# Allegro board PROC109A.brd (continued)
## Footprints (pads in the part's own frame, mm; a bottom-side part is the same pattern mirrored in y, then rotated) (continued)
HDR_2X5_61301021121_S_T_8-6
  rect 1.803x1.803 hole 1.118: 1(0,0)
  round 1.803 hole 1.118: 2(0,2.54) 3(2.54,0) 4(2.54,2.54) 5(5.08,0) 6(5.08,2.54) 7(7.62,0) 8(7.62,2.54) 9(10.16,0) 10(10.16,2.54)
IND4_DLW21H_90X60_SMD_1-4
  rect 0.889x0.356 smd: 1(-0.85,-0.425) 2(0.85,-0.425) 3(0.85,0.425) 4(-0.85,0.425)
IND0603_1
  rect 0.914x1.016 smd: 1(-0.8,0) 2(0.8,0)
IND0603_1#2
  rect 1.245x1.092 smd: 1(-0.85,0) 2(0.85,0)
IND0806_1-2
  rect 1.219x1.803 smd: 1(-0.85,0) 2(0.85,0)
LED4_150066RV54050_70X60_SMD_0-7
  rect 0.787x0.508 smd: 1(-0.8,-0.45) 2(0.8,-0.45) 3(0.8,0.45) 4(-0.8,0.45)
LED_0603
  rect 0.787x0.787 smd: 1(-0.749,0) 2(0.749,0)
LED_150040GS73220_40X20_SMD_0-4
  rect 0.406x0.457 smd: 1(-0.5,0) 2(0.5,0)
LED_150060SS75000_70X40_SMD_0-8
  rect 0.787x0.787 smd: 1(-0.8,0) 2(0.8,0)
MSOP10_19-68_120X120_1-1
  rect 1.448x0.305 smd: 1(-2.2,1) 2(-2.2,0.5) 3(-2.2,0) 4(-2.2,-0.5) 5(-2.2,-1) 6(2.2,-1) 7(2.2,-0.5) 8(2.2,0) 9(2.2,0.5) 10(2.2,1)
OSC4_ASEK_130X100_SMD_1-2
  rect 1.397x0.991 smd: 1(-1.1,-0.8) 2(1.1,-0.8) 3(1.1,0.8) 4(-1.1,0.8)
QFN16_19-68_120X120_1_EP1-6
  rect 0.838x0.254 smd: 1(-1.45,0.75) 2(-1.45,0.25) 3(-1.45,-0.25) 4(-1.45,-0.75) 9(1.45,-0.75) 10(1.45,-0.25) 11(1.45,0.25) 12(1.45,0.75)
  rect 0.254x0.838 smd: 5(-0.75,-1.45) 6(-0.25,-1.45) 7(0.25,-1.45) 8(0.75,-1.45) 13(0.75,1.45) 14(0.25,1.45) 15(-0.25,1.45) 16(-0.75,1.45)
  rect 1.6x1.6 smd: 17(0,0)
QFN16_19-68_160X140_1
  rect 0.864x0.279 smd: 1(-1.975,-0.75) 8(1.975,-0.75) 9(1.975,0.75) 16(-1.975,0.75)
  rect 0.279x0.864 smd: 2(-1.25,-1.725) 3(-0.75,-1.725) 4(-0.25,-1.725) 5(0.25,-1.725) 6(0.75,-1.725) 7(1.25,-1.725) 10(1.25,1.725) 11(0.75,1.725) 12(0.25,1.725) 13(-0.25,1.725) 14(-0.75,1.725) 15(-1.25,1.725)
  rect 2.54x2.057 smd: 17(0,0)
QFN20_19-68_160X160_1
  rect 0.889x0.305 smd: 1(-2.05,1) 2(-2.05,0.5) 3(-2.05,0) 4(-2.05,-0.5) 5(-2.05,-1) 11(2.05,-1) 12(2.05,-0.5) 13(2.05,0) 14(2.05,0.5) 15(2.05,1)
  rect 0.305x0.889 smd: 6(-1,-2.05) 7(-0.5,-2.05) 8(0,-2.05) 9(0.5,-2.05) 10(1,-2.05) 16(1,2.05) 17(0.5,2.05) 18(0,2.05) 19(-0.5,2.05) 20(-1,2.05)
  rect 2.794x2.794 smd: 21(0,0)
QFN24_19-68_220X140_1
  rect 0.838x0.279 smd: 1(-2.725,-0.75) 12(2.725,-0.75) 13(2.725,0.75) 24(-2.725,0.75)
  rect 0.279x0.838 smd: 2(-2.25,-1.725) 3(-1.75,-1.725) 4(-1.25,-1.725) 5(-0.75,-1.725) 6(-0.25,-1.725) 7(0.25,-1.725) 8(0.75,-1.725) 9(1.25,-1.725) 10(1.75,-1.725) 11(2.25,-1.725) 14(2.25,1.725) 15(1.75,1.725) 16(1.25,1.725) 17(0.75,1.725) 18(0.25,1.725) 19(-0.25,1.725) 20(-0.75,1.725) 21(-1.25,1.725) 22(-1.75,1.725) 23(-2.25,1.725)
  custom 0.508x0.508 smd: 25(0,0)
QFN48_19-68_280X280_1_EP4-2
  rect 0.838x0.305 smd: 1(-3.5,2.75) 2(-3.5,2.25) 3(-3.5,1.75) 4(-3.5,1.25) 5(-3.5,0.75) 6(-3.5,0.25) 7(-3.5,-0.25) 8(-3.5,-0.75) 9(-3.5,-1.25) 10(-3.5,-1.75) 11(-3.5,-2.25) 12(-3.5,-2.75) 25(3.5,-2.75) 26(3.5,-2.25) 27(3.5,-1.75) 28(3.5,-1.25) 29(3.5,-0.75) 30(3.5,-0.25) 31(3.5,0.25) 32(3.5,0.75) 33(3.5,1.25) 34(3.5,1.75) 35(3.5,2.25) 36(3.5,2.75)
  rect 0.305x0.838 smd: 13(-2.75,-3.5) 14(-2.25,-3.5) 15(-1.75,-3.5) 16(-1.25,-3.5) 17(-0.75,-3.5) 18(-0.25,-3.5) 19(0.25,-3.5) 20(0.75,-3.5) 21(1.25,-3.5) 22(1.75,-3.5) 23(2.25,-3.5) 24(2.75,-3.5) 37(2.75,3.5) 38(2.25,3.5) 39(1.75,3.5) 40(1.25,3.5) 41(0.75,3.5) 42(0.25,3.5) 43(-0.25,3.5) 44(-0.75,3.5) 45(-1.25,3.5) 46(-1.75,3.5) 47(-2.25,3.5) 48(-2.75,3.5)
  rect 4.191x4.191 smd: 49(0,0)
RECPT_2X10_CRD-081413-A_S_T_8-6
  rect 1.88x1.88 hole 1.168: 1(0,0)
  round 1.88 hole 1.168: 2(0,-2.54) 3(2.54,0) 4(2.54,-2.54) 5(5.08,0) 6(5.08,-2.54) 7(7.62,0) 8(7.62,-2.54) 9(10.16,0) 10(10.16,-2.54) 11(12.7,0) 12(12.7,-2.54) 13(15.24,0) 14(15.24,-2.54) 15(17.78,0) 16(17.78,-2.54) 17(20.32,0) 18(20.32,-2.54) 19(22.86,0) 20(22.86,-2.54)
RES0201_0-5
  rect 0.457x0.432 smd: 1(-0.33,0) 2(0.33,0)
RES0402_0-5
  rect 0.559x0.635 smd: 1(-0.49,0) 2(0.49,0)
RES0406_0-5
  rect 0.559x1.753 smd: 1(-0.49,0) 2(0.49,0)
RES0603_0-75
  rect 0.635x0.991 smd: 1(-0.74,0) 2(0.74,0)
SC70-5_1-1
  rect 0.94x0.406 smd: 1(-1.1,0.65) 2(-1.1,0) 3(-1.1,-0.65) 4(1.1,-0.65) 5(1.1,0.65)
SC70-6
  rect 0.94x0.406 smd: 1(-1.1,0.65) 2(-1.1,0) 3(-1.1,-0.65) 4(1.1,-0.65) 5(1.1,0) 6(1.1,0.65)
SOIC16_1-8
  rect 1.549x0.61 smd: 1(-2.7,4.445) 2(-2.7,3.175) 3(-2.7,1.905) 4(-2.7,0.635) 5(-2.7,-0.635) 6(-2.7,-1.905) 7(-2.7,-3.175) 8(-2.7,-4.445) 9(2.7,-4.445) 10(2.7,-3.175) 11(2.7,-1.905) 12(2.7,-0.635) 13(2.7,0.635) 14(2.7,1.905) 15(2.7,3.175) 16(2.7,4.445)
SOIC16_W_2-7
  rect 2.007x0.61 smd: 1(-4.65,4.445) 2(-4.65,3.175) 3(-4.65,1.905) 4(-4.65,0.635) 5(-4.65,-0.635) 6(-4.65,-1.905) 7(-4.65,-3.175) 8(-4.65,-4.445) 9(4.65,-4.445) 10(4.65,-3.175) 11(4.65,-1.905) 12(4.65,-0.635) 13(4.65,0.635) 14(4.65,1.905) 15(4.65,3.175) 16(4.65,4.445)
SON6_25-59_85X85_0-8
  rect 0.61x0.356 smd: 1(-1.05,0.65) 2(-1.05,0) 3(-1.05,-0.65) 4(1.05,-0.65) 5(1.05,0) 6(1.05,0.65)
  rect 1.092x1.702 smd: 7(0,0)
SON6_CSD17313Q2_80X80
  rect 0.406x0.457 smd: 1(-0.65,-0.922) 2(0,-0.922) 3(0.65,-0.922) 4(0.65,0.922) 5(0,0.922) 6(-0.65,0.922)
  rect 0.406x0.864 smd: 7(0.65,0.096)
  rect 1.041x1.092 smd: 8(-0.325,0)
SON8_25-59_130X130_1
  rect 0.762x0.356 smd: 1(-1.45,0.975) 2(-1.45,0.325) 3(-1.45,-0.325) 4(-1.45,-0.975) 5(1.45,-0.975) 6(1.45,-0.325) 7(1.45,0.325) 8(1.45,0.975)
  rect 1.753x2.515 smd: 9(0,0)
SOT23-5
  rect 1.092x0.61 smd: 1(-1.3,0.95) 2(-1.3,0) 3(-1.3,-0.95) 4(1.3,-0.95) 5(1.3,0.95)
SOT23-5_1-5
  rect 1.295x0.66 smd: 1(-1.4,0.95) 2(-1.4,0) 3(-1.4,-0.95) 4(1.4,-0.95) 5(1.4,0.95)
SOT23-5_1-5#2
  rect 1.092x0.61 smd: 1(-1.3,0.95) 2(-1.3,0) 3(-1.3,-0.95) 4(1.3,-0.95) 5(1.3,0.95)
SOT23-123_1-2
  rect 1.016x0.61 smd: 1(-1.15,0.95) 2(-1.15,-0.95) 3(1.15,0)
SOT553-5_0-6
  rect 0.762x0.305 smd: 1(-0.79,0.5) 2(-0.79,0) 3(-0.79,-0.5) 4(0.79,-0.5) 5(0.79,0.5)
SW4_436331045822_190X190_SMD_1-7
  round 0.686 hole 0.813 unplated: (0,1.375) (0,-1.375)
  rect 1.194x0.991 smd: 1(2.8,0.85) 2(2.8,-0.85) 3(-2.8,0.85) 4(-2.8,-0.85)
SW16_416131160808_460X230_SMD_2-7
  rect 0.762x1.27 smd: 1(-4.445,-3.81) 2(-3.175,-3.81) 3(-1.905,-3.81) 4(-0.635,-3.81) 5(0.635,-3.81) 6(1.905,-3.81) 7(3.175,-3.81) 8(4.445,-3.81) 9(4.445,3.81) 10(3.175,3.81) 11(1.905,3.81) 12(0.635,3.81) 13(-0.635,3.81) 14(-1.905,3.81) 15(-3.175,3.81) 16(-4.445,3.81)
SW_TDA01H0S_240X90_SMD_2-3
  rect 1.27x0.762 smd: 1(-3.81,0) 2(3.81,0)
TP20_SMD
  round 0.508 smd: 1(0,0)
TP40_SMD
  round 1.016 smd: 1(0,0)
TP_40X65
  round 1.651 hole 1.016: 1(0,0)
TQFN42_19-68_140X360_0-8
  rect 0.838x0.305 smd: 1(-1.7,4) 2(-1.7,3.5) 3(-1.7,3) 4(-1.7,2.5) 5(-1.7,2) 6(-1.7,1.5) 7(-1.7,1) 8(-1.7,0.5) 9(-1.7,0) 10(-1.7,-0.5) 11(-1.7,-1) 12(-1.7,-1.5) 13(-1.7,-2) 14(-1.7,-2.5) 15(-1.7,-3) 16(-1.7,-3.5) 17(-1.7,-4) 22(1.7,-4) 23(1.7,-3.5) 24(1.7,-3) 25(1.7,-2.5) 26(1.7,-2) 27(1.7,-1.5) 28(1.7,-1) 29(1.7,-0.5) 30(1.7,0) 31(1.7,0.5) 32(1.7,1) 33(1.7,1.5) 34(1.7,2) 35(1.7,2.5) 36(1.7,3) 37(1.7,3.5) 38(1.7,4)
  rect 0.305x0.838 smd: 18(-0.75,-4.45) 19(-0.25,-4.45) 20(0.25,-4.45) 21(0.75,-4.45) 39(0.75,4.45) 40(0.25,4.45) 41(-0.25,4.45) 42(-0.75,4.45)
  rect 2.159x7.645 smd: 43(0,0)
TQFP128_15-74_550X550_1-2
  rect 1.499x0.203 smd: 1(-7.7,6.2) 2(-7.7,5.8) 3(-7.7,5.4) 4(-7.7,5) 5(-7.7,4.6) 6(-7.7,4.2) 7(-7.7,3.8) 8(-7.7,3.4) 9(-7.7,3) 10(-7.7,2.6) 11(-7.7,2.2) 12(-7.7,1.8) 13(-7.7,1.4) 14(-7.7,1) 15(-7.7,0.6) 16(-7.7,0.2) 17(-7.7,-0.2) 18(-7.7,-0.6) 19(-7.7,-1) 20(-7.7,-1.4) 21(-7.7,-1.8) 22(-7.7,-2.2) 23(-7.7,-2.6) 24(-7.7,-3) 25(-7.7,-3.4) 26(-7.7,-3.8) 27(-7.7,-4.2) 28(-7.7,-4.6) 29(-7.7,-5) 30(-7.7,-5.4) 31(-7.7,-5.8) 32(-7.7,-6.2) 65(7.7,-6.2) 66(7.7,-5.8) 67(7.7,-5.4) 68(7.7,-5) 69(7.7,-4.6) 70(7.7,-4.2) 71(7.7,-3.8) 72(7.7,-3.4) 73(7.7,-3) 74(7.7,-2.6) 75(7.7,-2.2) 76(7.7,-1.8) 77(7.7,-1.4) 78(7.7,-1) 79(7.7,-0.6) 80(7.7,-0.2) 81(7.7,0.2) 82(7.7,0.6) 83(7.7,1) 84(7.7,1.4) 85(7.7,1.8) 86(7.7,2.2) 87(7.7,2.6) 88(7.7,3) 89(7.7,3.4) 90(7.7,3.8) 91(7.7,4.2) 92(7.7,4.6) 93(7.7,5) 94(7.7,5.4) 95(7.7,5.8) 96(7.7,6.2)
  rect 0.203x1.499 smd: 33(-6.2,-7.7) 34(-5.8,-7.7) 35(-5.4,-7.7) 36(-5,-7.7) 37(-4.6,-7.7) 38(-4.2,-7.7) 39(-3.8,-7.7) 40(-3.4,-7.7) 41(-3,-7.7) 42(-2.6,-7.7) 43(-2.2,-7.7) 44(-1.8,-7.7) 45(-1.4,-7.7) 46(-1,-7.7) 47(-0.6,-7.7) 48(-0.2,-7.7) 49(0.2,-7.7) 50(0.6,-7.7) 51(1,-7.7) 52(1.4,-7.7) 53(1.8,-7.7) 54(2.2,-7.7) 55(2.6,-7.7) 56(3,-7.7) 57(3.4,-7.7) 58(3.8,-7.7) 59(4.2,-7.7) 60(4.6,-7.7) 61(5,-7.7) 62(5.4,-7.7) 63(5.8,-7.7) 64(6.2,-7.7) 97(6.2,7.7) 98(5.8,7.7) 99(5.4,7.7) 100(5,7.7) 101(4.6,7.7) 102(4.2,7.7) 103(3.8,7.7) 104(3.4,7.7) 105(3,7.7) 106(2.6,7.7) 107(2.2,7.7) 108(1.8,7.7) 109(1.4,7.7) 110(1,7.7) 111(0.6,7.7) 112(0.2,7.7) 113(-0.2,7.7) 114(-0.6,7.7) 115(-1,7.7) 116(-1.4,7.7) 117(-1.8,7.7) 118(-2.2,7.7) 119(-2.6,7.7) 120(-3,7.7) 121(-3.4,7.7) 122(-3.8,7.7) 123(-4.2,7.7) 124(-4.6,7.7) 125(-5,7.7) 126(-5.4,7.7) 127(-5.8,7.7) 128(-6.2,7.7)
TSSOP8_25-59_125X180_1-2
  rect 1.499x0.457 smd: 1(-2.9,0.975) 2(-2.9,0.325) 3(-2.9,-0.325) 4(-2.9,-0.975) 5(2.9,-0.975) 6(2.9,-0.325) 7(2.9,0.325) 8(2.9,0.975)
TSSOP14_25-59_205X180_1-2
  rect 1.499x0.457 smd: 1(-2.9,1.95) 2(-2.9,1.3) 3(-2.9,0.65) 4(-2.9,0) 5(-2.9,-0.65) 6(-2.9,-1.3) 7(-2.9,-1.95) 8(2.9,-1.95) 9(2.9,-1.3) 10(2.9,-0.65) 11(2.9,0) 12(2.9,0.65) 13(2.9,1.3) 14(2.9,1.95)
TSSOP16_25-59_205X180
  rect 1.6x0.356 smd: 1(-2.8,2.275) 2(-2.8,1.625) 3(-2.8,0.975) 4(-2.8,0.325) 5(-2.8,-0.325) 6(-2.8,-0.975) 7(-2.8,-1.625) 8(-2.8,-2.275) 9(2.8,-2.275) 10(2.8,-1.625) 11(2.8,-0.975) 12(2.8,-0.325) 13(2.8,0.325) 14(2.8,0.975) 15(2.8,1.625) 16(2.8,2.275)
unnamed
  round 0.686 hole 0.813 unplated: (-1.27,1.254) (0,1.254) (1.27,1.254)
unnamed#2
  round 3.073 hole 3.2 unplated: (0,0)
unnamed#4
  round 0.686 hole 0.813 unplated: (-1.27,1.254) (-1.27,-1.254) (0,1.254) (0,-1.254) (1.27,1.254) (1.27,-1.254)
UQFN16_TMUX1574_70X100_0-6
  rect 0.711x0.203 smd: 1(-0.75,0.6)
  rect 0.61x0.203 smd: 2(-0.8,0.2) 3(-0.8,-0.2) 4(-0.8,-0.6) 9(0.8,-0.6) 10(0.8,-0.2) 11(0.8,0.2) 12(0.8,0.6)
  rect 0.203x0.61 smd: 5(-0.6,-1.2) 6(-0.2,-1.2) 7(0.2,-1.2) 8(0.6,-1.2) 13(0.6,1.2) 14(0.2,1.2) 15(-0.2,1.2) 16(-0.6,1.2)
USON10_TPD4E05U_40X100_0-6
  rect 0.559x0.305 smd: 1(-0.385,1) 2(-0.385,0.5) 4(-0.385,-0.5) 5(-0.385,-1) 6(0.385,-1) 7(0.385,-0.5) 9(0.385,0.5) 10(0.385,1)
  rect 0.559x0.406 smd: 3(-0.385,0) 8(0.385,0)
VSON10_TPS74801-Q1_120X120_1
  rect 0.61x0.229 smd: 1(-1.4,1) 2(-1.4,0.5) 3(-1.4,0) 4(-1.4,-0.5) 5(-1.4,-1) 6(1.4,-1) 7(1.4,-0.5) 8(1.4,0) 9(1.4,0.5) 10(1.4,1)
  custom 0.412x0.412 smd: 11(0,0)
VSONHR8_TPS62823_60X80_1
  rect 0.559x0.254 smd: 1(-0.675,0.75) 2(-0.675,0.25) 3(-0.675,-0.25) 4(-0.675,-0.75) 5(0.675,-0.75) 6(0.675,-0.25) 7(0.675,0.25) 8(0.675,0.75)
VSSOP8_19-68_85X95_0-9
  rect 1.041x0.305 smd: 1(-1.65,0.75) 2(-1.65,0.25) 3(-1.65,-0.25) 4(-1.65,-0.75) 5(1.65,-0.75) 6(1.65,-0.25) 7(1.65,0.25) 8(1.65,0.75)
VSSOP8_25-59_120X120_1-1
  rect 1.397x0.457 smd: 1(-2.2,0.975) 2(-2.2,0.325) 3(-2.2,-0.325) 4(-2.2,-0.975) 5(2.2,-0.975) 6(2.2,-0.325) 7(2.2,0.325) 8(2.2,0.975)
WSON6_CSD13202Q2_80X80_0-8
  rect 0.457x0.305 smd: 1(-0.975,0.65) 2(-0.975,0) 3(-0.975,-0.65) 4(0.975,-0.65) 5(0.975,0) 6(0.975,0.65)
  rect 0.762x0.305 smd: 7(0.095,-0.65)
  rect 0.991x0.94 smd: 8(0,0.325)
WSON8_19-68_80X80_0-8
  rect 0.813x0.305 smd: 1(-1.1,0.75) 2(-1.1,0.25) 3(-1.1,-0.25) 4(-1.1,-0.75) 5(1.1,-0.75) 6(1.1,-0.25) 7(1.1,0.25) 8(1.1,0.75)
  rect 0.991x1.702 smd: 9(0,0)
X2QFN12_TUSB322I_60X60_0-4
  rect 0.711x0.203 smd: 1(-0.65,0.2) 2(-0.65,-0.2) 7(0.65,-0.2) 8(0.65,0.2)
  rect 0.203x0.508 smd: 3(-0.6,-0.75) 4(-0.2,-0.75) 5(0.2,-0.75) 6(0.6,-0.75) 9(0.6,0.75) 10(0.2,0.75) 11(-0.2,0.75) 12(-0.6,0.75)
X2SON8_15-74_70X50
  rect 0.838x0.203 smd: 1(-0.55,0.6) 2(-0.55,0.2) 3(-0.55,-0.2) 4(-0.55,-0.6) 5(0.55,-0.6) 6(0.55,-0.2) 7(0.55,0.2) 8(0.55,0.6)
XTAL4_LFXTAL055474_130X110_SMD_0-8
  rect 1.397x1.143 smd: 1(-1.1,-0.8) 2(1.1,-0.8) 3(1.1,0.8) 4(-1.1,0.8)

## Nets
0V85_EN: R125.1 R127.2 U21.1
DGND: C1.2 C2.2 C3.1 C4.2 C5.2 C6.2 C7.2 C8.2 C9.1 C10.2 C11.2 C12.2 C13.2 C14.2 C15.2 C16.1 C17.2 C18.2 C19.2 C20.2 C21.2 C22.2 C23.2 C24.2 C25.2 C26.2 C27.2 C28.2 C29.2 C30.1 C31.2 C32.2 C33.2 C34.2 C35.2 C36.2 C37.2 C38.2 C39.2 C41.2 C42.2 C43.2 C44.2 C45.2 C46.2 C47.2 C48.2 C49.2 C50.2 C51.2 C52.2 C53.2 C54.2 C55.2 C56.2 C57.2 C58.2 C59.2 C60.2 C61.2 C63.2 C64.2 C65.2 C66.2 C67.2 C68.2 C69.2 C70.2 C71.2 C72.2 C73.2 C74.2 C75.2 C76.2 C77.2 C78.2 C79.2 C80.2 C81.2 C82.2 C84.2 C85.2 C86.2 C88.2 C90.2 C91.2 C92.2 C93.2 C94.2 C95.2 C96.2 C97.2 C98.2 C99.2 C100.2 C101.2 C102.2 C103.2 C104.2 C105.2 C106.2 C107.2 C108.2 C109.2 C110.2 C111.2 C112.1 C113.2 C114.2 C116.2 C117.2 C118.2 C119.2 C120.1 C121.2 C122.2 C123.2 C124.2 C125.2 C126.2 C128.2 C129.2 C130.2 C131.1 C132.2 C133.2 C134.2 C135.2 C136.2 C137.2 C138.2 C139.2 C140.2 C141.2 C142.2 C143.2 C144.2 C145.2 C146.2 C147.2 C148.2 C149.2 C150.2 C151.2 C152.2 C153.2 C154.2 C155.2 C156.2 C157.2 C158.2 C159.2 C160.2 C161.2 C162.2 C163.2 C165.2 C166.2 C167.2 C168.2 C169.2 C170.2 C171.2 C172.2 C173.2 C174.2 C175.2 C176.2 C177.2 C178.2 C179.2 C180.2 C181.2 C182.2 C183.2 C184.2 C185.2 C186.2 C187.2 C188.2 C189.2 C190.2 C191.2 C192.2 C193.2 C194.2 C196.2 C197.2 C198.2 C199.2 C200.2 C201.2 C202.2 C203.2 C204.2 C205.2 C206.2 C207.2 C208.2 C209.2 C210.2 C211.2 C212.2 C213.2 C214.2 C215.2 C216.2 C217.2 C218.2 C219.2 C220.2 C221.2 C222.2 C223.2 C224.2 C225.2 C226.2 C227.2 C228.2 C229.2 C230.2 C231.2 C232.2 C233.2 C234.2 C235.2 C236.2 C237.2 C238.2 C239.2 C240.2 C241.2 C242.2 C243.2 C244.2 C245.2 C246.2 C247.2 C248.2 C249.2 C250.2 C251.2 C252.2 C253.2 C254.2 C255.2 C256.2 C257.2 C258.2 C259.2 C260.2 C262.2 C263.2 C265.1 C266.2 C267.2 C268.2 C269.2 C270.2 C271.1 C272.1 C273.1 D1.2 D2.2 D3.1 D4.2 D5.2 D6.2 D7.2 D8.2 J1.4 J2.2 J5.4 J6.2 J9.2 J9.3 J10.A1 J10.A12 J10.B1 J10.B12 J10.G1 J10.G2 J11.2 J12.5 J13.1 J14.2 J14.3 J15.7 J15.16 J15.25 J15.34 J15.40 J15.41 J15.42 J16.3 J16.4 J17.1 J18.1 J19.1 J20.5 J21.5 LD6.1(CATHODE) LD7.1(CATHODE) LD10.1(CATHODE) LD11.1(CATHODE) LD17.1(CATHODE) Q3.4 Q3.7(S2) Q4.4 Q4.7(S2) Q5.4 Q5.7(S2) Q6.4 Q6.7(S2) Q7.4 Q7.7 Q8.4 Q8.7 Q9.4 Q9.7(S2) Q10.4 Q10.7(S2) Q11.4 Q11.7(S2) Q12.4 Q12.7(S2) Q13.4 Q13.7(S2) Q14.4 Q14.7(S2) Q15.4 Q15.7(S2) Q16.4 Q16.7 R9.1 R16.2 R22.2 R24.1 R27.2 R33.2 R47.2 R49.1 R52.2 R54.2 R64.2 R66.2 R69.2 R71.2 R72.2 R74.2 R75.2 R76.2 R77.2 R78.1 R83.1 R87.1 R90.1 R92.1 R102.2 R116.1 R119.1 R120.1 R121.1 R122.1 R123.2 R124.2 R125.2 R126.1 R128.1 R132.2 R133.2 R137.2 R138.2 R139.2 R142.2 R145.2 R147.2 R149.2 R151.2 R153.2 R155.2 R157.2 R159.2 R160.2 R165.1 R172.1 R173.1 R174.1 R175.1 R177.1 R184.2 R190.1 R195.2 R199.2 R200.2 R203.1 R204.1 R205.1 R206.1 R207.1 R208.1 R212.2 R221.2 R228.2 R232.2 R234.1 R239.2 R241.1 R242.2 R243.1 R245.1 R247.2 R250.1 R253.2 R255.2 R256.2 R260.2 R267.2 R276.1 R589.1 R591.1 R592.2 R600.2 SW1.2 SW1.4 SW2.2 SW2.4 SW3.2 SW3.4 SW5.2 SW5.4 SW6.1 TP2.1(TP) TP9.1(TP) TP36.1(TP) TP37.1(TP) TP38.1(TP) U1.2 U2.10(VSS) U3.2 U4.10 U4.11 U4.12 U4.13 U4.25 U5.5 U5.7 U6.4 U7.49 U8.1 U8.4 U8.7 U8.10 U8.13 U9.4 U10.3 U10.5 U11.3 U12.1 U12.4 U12.7 U12.10 U12.13 U13.4 U14.2 U15.3 U16.2 U17.4 U18.A1 U18.A2 U18.A20 U18.A21 U18.AA1 U18.AA2 U18.AA20 U18.AA21 U18.B1 U18.B21 U18.D10 U18.D16 U18.D17 U18.E6 U18.E11 U18.E13 U18.F8 U18.F17 U18.G16 U18.H6 U18.H7 U18.H16 U18.J5 U18.J6 U18.J11 U18.J16 U18.K6 U18.K7 U18.K8 U18.K16 U18.L10 U18.L11 U18.L12 U18.M7 U18.M15 U18.M16 U18.N6 U18.N11 U18.N13 U18.P7 U18.P11 U18.P15 U18.P16 U18.R6 U18.R11 U18.T14 U18.U6 U18.Y1 U18.Y21(VSS#Y21) U19.49 U20.10 U20.11 U21.3 U21.5 U22.5 U22.9 U23.5 U23.9 U24.3 U24.8 U25.2 U25.3 U25.8 U25.9 U25.14 U25.15 U26.6 U26.17 U27.12 U27.21 U28.3 U30.5 U30.9 U31.3 U32.7 U32.9 U32.10 U33.6 U33.11 U34.3 U35.8 U35.16 U36.1 U37.10 U37.17 U37.48 U37.55 U37.58 U37.64 U37.66 U37.80 U37.114 U38.3 U38.7 U39.6 U39.11 U40.43 U41.2 U42.3 U42.4 U42.5 U42.6 U43.3 U44.2 U44.9 U45.3 U45.5 U45.7 U45.8 U45.9 U45.10 U45.12 U45.14 U45.15 U46.9 U46.17 U50.6 U50.13 U51.6 U51.13 U52.6 U52.13 Y1.2 Y1.4
VBAT_XDS: C208.1 R249.2 U37.68
VBUS_DETECT: R113.1 U20.4
VBUS_TYPEC: C68.1 C70.1 D8.1(CATHODE) FL1.1 J10.A4 J10.A9 J10.B4 J10.B9(VBUS4) TP32.1(TP)
VBUS_XDS_USB: C170.1 J20.1(VBUS) R219.1 R222.2 TP27.1(TP) U24.1 U24.10(NC4) U38.4 U38.6
VCC3V3_TA: C5.1 C31.1 C85.1 C88.1 C146.1 C155.1 C243.1 J15.1 J15.2 J15.3 R17.2 R28.2 R34.2 R48.2 R53.2 R67.2 R70.2 R178.1 R182.1 R186.1 R187.1 R189.2 R191.2 R196.2 R197.2 R202.2 R209.2 TP49.1(TP) U4.1 U4.2 U9.5 U9.8(VCCB) U26.14(VCCP) U26.15 U28.5 U41.5(OUT)
VCC3V3_XDS: C44.1 C60.1 C104.1 C121.1 C151.1 C154.1 C180.1 C181.1 C182.1 C191.1 C240.1 C242.1 C260.1 C262.1 R98.2 R99.2 R100.2 R101.2 R108.2 R109.2 R235.1 R246.1 R249.1 TP35.1(TP) U16.7(VCCB) U25.16(VCCB) U37.7 U37.8 U37.16 U37.26 U37.28 U37.39 U37.47 U37.51 U37.52 U37.69 U37.79 U37.90 U37.101 U37.113 U37.122 U38.1 U42.8(VCCB) U45.16(VCCB)
VCC_5V0_CAN: C257.1 R270.2 TP50.1(TP) U44.3(VCC)
VDD_1V1: C17.1 C19.1 C34.1 C55.1 C56.1 C61.1 C95.1 C96.1 C97.1 C98.1 C113.1 C216.1 C217.1 C221.1 C222.1 C228.1 C229.1 C256.1 R248.1 TP30.1(TP) U7.6 U7.31 U7.39 U19.6 U19.31 U19.39 U39.9 U39.10
VDD_1V1_SS: C183.1 U39.7(SS)
VDD_1V8: C30.2 C162.1 FB1.1 FB2.1 FB5.1 FB6.1 FB7.1 FB8.1 FB9.1 R29.2 R30.2 R198.1 TP5.1(TP) U11.5 U18.F14
VDD_1V8_CT: C80.1 U27.5
VDD_1V8_ENABLE: R31.1 R224.1 U10.8
VDD_1V8_R: C18.1 C20.1 R30.1 U5.1
VDD_1V8_SENSE: R198.2 R199.1 U27.10
VDD_2V5: C11.1 C23.1 C53.1 C58.1 C92.1 C99.1 C100.1 C107.1 C125.1 C130.1 C197.1 C230.1 C231.1 C238.1 R81.2 R233.1 TP20.1(TP) U7.3 U7.9 U19.3 U19.9 U33.9 U33.10
VDD_2V5_PG: R81.1 U33.3 U39.5
VDD_2V5_SS: C111.1 U33.7(SS)
VDD_CORE_0V85: C48.1 C49.1 C52.1 C62.1 C136.1 C137.1 C138.1 C139.1 C163.1 C165.1 C186.1 C187.1 C188.1 C199.1 C200.1 C201.1 C211.1 C212.1 C214.1 C227.1 C234.1 C239.1 C244.1 C247.1 C250.1 C251.1 C254.1 C255.1 R96.1 R130.1 R176.2 TP23.1(TP) U18.F11 U18.G5 U18.G6 U18.G10 U18.H8 U18.H15 U18.J9 U18.J10 U18.J12 U18.K11 U18.K14 U18.L9 U18.L13 U18.M8 U18.M14 U18.N9 U18.N10 U18.P8 U18.P14 U18.R9 U18.R10 U18.R12 U18.R13 U18.V16
VDD_CORE_0V85_EN: R29.1 R127.1 U5.3(PG)
VDD_CORE_0V85_FB: C62.2 R124.1 R130.2 U21.2
VDD_CORE_0V85_H_SENSE: R6.1 R175.2 U27.6
VDD_CORE_0V85_L_SENSE: R6.2 R176.1 U27.7
VDD_CORE_0V85_PG: Q3.3 R112.1 U21.8
VDD_CORE_0V85_R: C50.1 L2.2 R96.2
VDD_CORE_0V85_SW: L2.1 U21.6
VDDA_1P8_USB0: C176.1 C177.1 C179.1 FB5.2 TP47.1(TP) U18.U15
VDDA_1V8: C4.1 C126.1 C135.1 C144.1 C153.1 FB2.2 R15.2 TP40.1(TP) U1.5 U18.F18 U18.H14
VDDA_3P3_USB0: C156.1 C157.1 C178.1 FB4.2 TP45.1(TP) U18.U16
VDDA_3V3: C142.1 C174.1 FB3.2 TP43.1(TP) U18.K15
VDDA_ADC: C109.1 C116.1 C147.1 C148.1 FB1.2 TP48.1(TP) U18.G17 U18.H17
VDDA_PLL0: C185.1 C204.1 C206.1 FB7.2 TP41.1(TP) U18.N12
VDDA_PLL1: C210.1 C236.1 C241.1 FB9.2 TP44.1(TP) U18.G9
VDDA_PLL2: C184.1 C193.1 C194.1 FB6.2 TP46.1(TP) U18.G12
VDDA_TEMP: C190.1 C198.1 C224.1 C225.1 FB8.2 TP42.1(TP) U18.G11 U18.M11
VDDC_1V2_XDS: C102.1 C105.1 C132.1 U37.87 U37.115
VDDSHV_3V3: C133.1 C134.1 C140.1 C141.1 C145.1 C158.1 C167.1 C168.1 C169.1 C171.1 C175.1 C189.1 C202.1 C203.1 C205.1 C213.1 C215.1 C235.1 C237.1 C245.1 C246.1 C249.1 C253.1 R261.2 TP52.1(TP) U18.C13 U18.D13 U18.E7 U18.E8 U18.E9 U18.E14 U18.E15 U18.L6 U18.M6 U18.N16 U18.N17 U18.P5 U18.P6 U18.R17 U18.T8 U18.T11 U18.T17 U18.U7 U18.U8 U18.U11
VDDSHV_SDIO: C143.1 C160.1 C172.1 R19.2 R21.2 R192.2 R193.2 R194.2 U18.J17 U18.L16 U18.L17
BOARD_POWER_EN: R84.2 R85.1 U10.1
BOOTMODE0: R39.1 R55.2 R208.2
BOOTMODE0_R: R55.1 U18.R21 U32.1
BOOTMODE1: R40.1 R56.2 R207.2
BOOTMODE2: R41.1 R206.2 R215.2
BOOTMODE2_R: R215.1 U18.T19 U32.6
BOOTMODE3: R42.2 U4.21
BOOTMODE4: R59.2 U4.20
BOOTMODE5: R57.2 U4.19
BOOTMODE6: R217.2 U4.18
BOOTMODE7: R216.2 U4.17
BOOTMODE8: R214.2 U4.16
BOOTMODE8_R: R214.1 U18.U18 U32.3
BOOTMODE9: R58.2 U4.15
BOOTMODE9_R: R58.1 U18.U20 U32.4
BOOTMODE10: R43.1 R60.2 R205.2
BOOTMODE10_R: R60.1 U18.V20 U32.5
BOOTMODE11: R44.1 R61.2 R204.2
BOOTMODE12: R45.1 R62.2 R203.2
BOOTMODE14: R586.2 R588.1 R589.2
BOOTMODE15: R587.2 R590.1 R591.2
BOOTMODEON: R24.2 U4.22 U28.4(Y)
BP_3V3: J5.1 R163.2
BP_5V0: J5.2 R161.1
BP_ADC0_AIN0: J1.3 R143.1
BP_ADC0_AIN1: J1.11 R152.1
BP_ADC0_AIN2: J1.6 R144.1
BP_ADC0_AIN3: J1.8 R146.1
BP_ADC0_AIN4: J1.10 R148.1
BP_ADC0_AIN5: J1.12 R150.1
BP_ADC0_AIN6: J1.14 R154.1
BP_ADC0_AIN7: J1.16 R156.1
BP_CONN_1_PORZ: J2.10 R8.1
BP_CONN_2_PORZ: J6.10 R2.1
BPSERVO_MUX_SEL: R598.1 SW6.2 U50.15 U51.15 U52.15
CAP_VDDS0: C192.1 U18.D12
CAP_VDDS1: C233.1 U18.N5
CAP_VDDS2: C196.1 U18.U9
CAP_VDDS3: C173.1 U18.R16
CAP_VDDS4: C149.1 U18.N18
CAP_VDDS5: C150.1 U18.M18
CAP_VDDS_MCU: C223.1 U18.D9
CORE_0V85_CT: C82.1 U27.2
CPSW_RGMII1_RD0: U18.T5 U40.28
CPSW_RGMII1_RD1: U18.R2 U40.26
CPSW_RGMII1_RD2: U18.U2 U40.24
CPSW_RGMII1_RD3: U18.T1 U40.22
CPSW_RGMII1_RX_CTL: U18.Y3 U40.20
CPSW_RGMII1_RXC: U18.U1 U40.18
CPSW_RGMII1_TD0: U18.Y14 U40.42
CPSW_RGMII1_TD1: R596.1 R597.1 U18.Y16
CPSW_RGMII1_TD1_MUX: R597.2 U40.40
CPSW_RGMII1_TD2: U18.U13 U40.37
CPSW_RGMII1_TD3: U18.AA14 U40.35
CPSW_RGMII1_TX_CTL: R594.1 R595.1 U18.W16
CPSW_RGMII1_TX_CTL_MUX: R595.2 U40.33
CPSW_RGMII1_TXC: R287.2 U40.31
DEBOUNCE_MCU_RESETZ: C1.1 D1.1(CATHODE) R1.1 SW2.1 SW2.3 U13.1
DEBOUNCE_SOC_RESET_REQZ: C2.1 D2.1(CATHODE) Q7.1 Q7.2 Q7.5 Q7.6 Q7.8(S5) R170.1 SW3.1 SW3.3 U13.6
DEBOUNCE_USER_INTN: C78.1 D4.1(CATHODE) Q16.1 Q16.2 Q16.5 Q16.6 Q16.8(S5) R164.1 SW5.1 SW5.3 U13.3
EEPROM_A1: R121.2 U17.2
EEPROM_A2: R122.2 U17.3
EEPROM_WP: R89.1 U17.7(WP)
EHRPWM0_A: J2.1 R42.1 U18.V21
EHRPWM0_B: J2.3 R59.1 U18.U21
EHRPWM0_TZN_IN0: J2.13 U32.11
EHRPWM1_A: J2.5 R57.1 U18.T20
EHRPWM1_B: J2.7 R217.1 U18.T18
EHRPWM2_A: J2.9 U30.3
EHRPWM2_B: J2.11 U30.7
EPHY1_XI: R13.2 R185.2 U7.20
EQEP1_A: C77.1 J12.1 R279.2 U46.16
EQEP1_A_LS: U18.L2 U46.1
EQEP1_B: C76.1 J12.2 R280.2 U46.14
EQEP1_B_LS: U18.L3 U46.3
EQEP1_I: C75.1 J12.3 R281.2 U46.13
EQEP1_I_LS: U18.R5 U46.4
EQEP2_A: C73.1 J21.1 R272.2 U46.12
EQEP2_A_LS: U18.B14 U46.5
EQEP2_B: C72.1 J21.2 R273.2 U46.11
EQEP2_B_LS: R244.2 U46.6
EQEP2_I: C71.1 J21.3 R274.2 U46.10
EQEP2_I_LS: U22.3 U46.7
ETH1_EARTH: C252.1 J19.15 J19.16 R253.1
ETH2_EARTH: C101.1 J18.15 J18.16 R200.1
FB_1V1: R247.1 R248.2 U39.8
FB_2V5: R232.1 R233.2 U33.8
FSI/BP_MUX_SEL: R61.1 R190.2 U18.W20 U30.1
FSI_RX0_CLK: J16.1 U30.2
FSI_RX0_D0: J16.5 U30.8
FSI_RX0_D1: J16.7 U32.12 U51.4
FSI_RX0CLK_PWM2A: U30.4 U32.14
FSI_RX0D0_PWM2B: U30.6 U32.13
FSI_TX0_CLK: J16.2 U18.P21 U51.1
FSI_TX0_D0: J16.6 R586.1 U18.Y18 U50.11
FSI_TX0_D1: J16.8 R587.1 U18.AA19
GPIO1_0: J2.15 U18.J3
GPIO1_1: J2.17 U18.J4
GPIO1_2: J2.19 U18.G1
GPIO1_3: J2.4 U18.H1
GPIO1_4: J2.8 U18.K2
GPIO1_5: J2.16 U18.F2
GPIO1_6: J5.15 U18.H2
GPIO1_8: J6.20 U18.H5
GPIO1_12: J1.9 U18.K1
GPIO1_18: J1.15 U18.K4 U50.1
GPIO1_19: J5.9 U18.G2
GPIO1_20: J2.20 U18.L5
GPIO1_21: J5.14 U18.J2
GPIO1_22: J5.16 U18.M2
GPIO1_26: J5.18 U18.F5
GPIO1_31: J5.20 U18.P1
GPIO1_32: J6.17 U18.P2
GPIO1_33: J6.19 U18.T4
GPIO1_35: J6.4 U18.M4
GPIO1_36: U18.T3 U52.3
GPIO1_36/PERIF_OUT_EN: J6.8 U52.5
GPIO1_40: J6.16 U18.E4
GPIO1_41: J6.18 U18.D2
GPIO1_61: TP34.1(TP) U22.7
GPIO1_77: J6.13 U18.B17
GPIO1_78: J6.15 U18.C16
GPIO_OSPI0_RESET_N: R181.1 U18.M20 U31.1
GPIO_RGMII1_PHY_RSTN: R275.1 U18.Y19 U43.1
GPIO_RGMII2_PHY_RSTN: R236.1 U18.Y15 U34.1
LED1: LD15.1(CATHODE) U35.3
LED2: LD14.1(CATHODE) U35.4
LED3: LD13.1(CATHODE) U35.5
LED4: LD12.1(CATHODE) U35.6
LED_DRV_A0: R245.2 U35.9
LED_DRV_A1: R241.2 U35.10
LED_DRV_A2: R243.2 U35.7
LMK_1G: R32.1 U6.2
LMK_CLK_IN: R26.2 U6.1
LMK_CLK_IN_R: R26.1 U3.3
MAIN_UART0_RXD: U18.B10 U45.6
MAIN_UART0_TXD: R592.1 U18.B11 U45.4
MAIN_UART1_CTS#: U12.11 U18.C11
MAIN_UART1_RTS#: U12.5 U18.A11
MAIN_UART1_RXD: U12.8 U18.B12
MAIN_UART1_TXD: U12.2 U18.A12
MAIN_UART2_RXD: J1.5 U32.16
MAIN_UART2_TXD: J1.7 R56.1 U18.R20
MAIN_UART4_RXD: U18.L1 U50.4 U50.9
MAIN_UART4_RXD/GPIO1_69: J5.5 U50.7
MAIN_UART4_TXD: J5.7 U18.E2
MCAN0_H: J11.1 R278.1 U44.7
MCAN0_L: J11.3 R277.2 U44.6
MCAN0_RX: R263.2 U44.4
MCAN0_RX_MUX: U18.A14 U22.6
MCAN0_RX_SYNC3_OUT: R131.1 R263.1 U22.8
MCAN0_STB: R276.2 U18.E3 U44.8
MCAN0_T: C267.1 R277.1 R278.2
MCAN0_TX: R259.2 U44.1
MCAN0_TX_EQEP2_I: U18.B13 U22.4
MCAN0_TX_SYNC2_OUT: R140.1 R259.1 U22.2
MCAN/EQEP_SEL/PERIF_OUT_EN: U18.F4 U52.4 U52.12
MCU_PORZ: TP1.1(TP) U1.4(Y) U18.C20
MCU_RESETSTATZ: R126.2 R180.1 TP31.1(TP) U18.A6
MCU_RESETZ: TP19.1(TP) U13.7 U18.A5
MCU_SAFTY_ERRZ: TP22.1(TP) U18.B20
MCU_UART0_CTS#: U8.11 U18.D4
MCU_UART0_RTS#: U8.5 U18.C2
MCU_UART0_RXD: U8.8 U18.D6
MCU_UART0_TXD: U8.2 U18.B2
OBSCLK0: R185.1 R240.2
OSC0: C131.2 U37.88 Y1.3
OSC0_XO: R78.2 U18.C21
OSC1: C120.2 U37.89 Y1.1
OSC_STB#: R49.2 U3.1
OSPI0_CLK: R54.1 R63.2 U2.16
OSPI0_CLK_R: R63.1 U18.P20
OSPI0_CS0_N: R183.1 U2.7 U18.L20
OSPI0_D0: R36.1 U2.15 U18.L19
OSPI0_D1: R10.1 U2.8 U18.N20
OSPI0_D2: R5.1 U2.9 U18.L21
OSPI0_D3: R37.1 U2.1 U18.N19
OSPI0_DQS: R213.1 U18.P17
OSPI0_DQS_R: R65.1 R213.2
OSPI0_LBCLKO: R65.2 U18.M21
PORZ_OUT: R87.2 R179.1 TP14.1(TP) U18.D18 U28.2 U32.8 U34.2 U43.2
PRG1_CPSW_ETH1_CLK_OUT: TP33.1(TP) U19.40
PRG1_CPSW_ETH1_D0M: J19.10 U19.2
PRG1_CPSW_ETH1_D0P: J19.9 U19.1
PRG1_CPSW_ETH1_D1M: J19.8 U19.5
PRG1_CPSW_ETH1_D1P: J19.7 U19.4
PRG1_CPSW_ETH1_D2M: J19.6 U19.8
PRG1_CPSW_ETH1_D2P: J19.5 U19.7
PRG1_CPSW_ETH1_D3M: J19.4 U19.11
PRG1_CPSW_ETH1_D3P: J19.3 U19.10
PRG1_CPSW_ETH1_LED1: J19.12 Q13.1 Q13.2 Q13.5 Q13.6 Q13.8
PRG1_CPSW_ETH1_LED2: J19.13 Q14.1 Q14.2 Q14.5 Q14.6 Q14.8 R252.1
PRG1_CPSW_ETH1_LED3: J19.14 Q15.1 Q15.2 Q15.5 Q15.6 Q15.8 R257.1
PRG1_CPSW_ETH1_LED_1000/RX_ER: Q14.3 R138.1 R265.2 U18.U14 U19.46
PRG1_CPSW_ETH1_LED_ACT: Q13.3 R137.1 R266.2 R594.2 U19.45
PRG1_CPSW_ETH1_LED_LINK: R139.1 R264.2 U18.Y13 U19.47
PRG1_CPSW_ETH1_RBIAS: R102.1 U19.12
PRG1_CPSW_ETH2_CLK_OUT: TP11.1(TP) U7.40
PRG1_CPSW_ETH2_D0M: J18.10 U7.2
PRG1_CPSW_ETH2_D0P: J18.9 U7.1
PRG1_CPSW_ETH2_D1M: J18.8 U7.5
PRG1_CPSW_ETH2_D1P: J18.7 U7.4
PRG1_CPSW_ETH2_D2M: J18.6 U7.8
PRG1_CPSW_ETH2_D2P: J18.5 U7.7
PRG1_CPSW_ETH2_D3M: J18.4 U7.11
PRG1_CPSW_ETH2_D3P: J18.3 U7.10
PRG1_CPSW_ETH2_LED1: J18.12 Q10.1 Q10.2 Q10.5 Q10.6 Q10.8
PRG1_CPSW_ETH2_LED2: J18.13 Q11.1 Q11.2 Q11.5 Q11.6 Q11.8 R220.1
PRG1_CPSW_ETH2_LED3: J18.14 Q12.1 Q12.2 Q12.5 Q12.6 Q12.8 R223.1
PRG1_CPSW_ETH2_LED_1000/RX_ER: Q11.3 R75.1 R226.2 U7.46 U18.AA11
PRG1_CPSW_ETH2_LED_ACT: Q10.3 R74.1 R227.2 R596.2 U7.45
PRG1_CPSW_ETH2_LED_LINK: R76.1 R225.2 U7.47 U18.W11
PRG1_CPSW_ETH2_RBIAS: R22.1 U7.12
PRG1_CPSW_RGMII1_CLK: R25.2 U19.20
PRG1_CPSW_RGMII1_CLK_R: R25.1 U6.8
PRG1_CPSW_RGMII1_GPIO_1: Q15.3 R95.2 R242.1 U19.22
PRG1_CPSW_RGMII1_RD0: R123.1 R254.2 U19.33 U40.11
PRG1_CPSW_RGMII1_RD1: R129.2 R260.1 U19.34 U40.12
PRG1_CPSW_RGMII1_RD2: R132.1 R269.2 U19.35 U40.13
PRG1_CPSW_RGMII1_RD3: R133.1 R268.2 U19.36 U40.14
PRG1_CPSW_RGMII1_RSTN: U19.43 U43.4(Y)
PRG1_CPSW_RGMII1_RX_CTL: R134.2 R267.1 U19.38 U40.15
PRG1_CPSW_RGMII1_RXC: R115.1 U40.16
PRG1_CPSW_RGMII1_RXC_R: R115.2 U19.32
PRG1_CPSW_RGMII1_TD0: U19.28 U40.2
PRG1_CPSW_RGMII1_TD1: U19.27 U40.3
PRG1_CPSW_RGMII1_TD2: U19.26 U40.4
PRG1_CPSW_RGMII1_TD3: U19.25 U40.5
PRG1_CPSW_RGMII1_TX_CTL: U19.37 U40.6
PRG1_CPSW_RGMII1_TXC: U19.29 U40.7
PRG1_CPSW_RGMII2_CLK: R13.1 R50.2
PRG1_CPSW_RGMII2_CLK_R: R50.1 U6.5(Y2)
PRG1_CPSW_RGMII2_GPIO_1: Q12.3 R12.2 R184.1 U7.22
PRG1_CPSW_RGMII2_RD0: R64.1 R218.2 U7.33 U18.AA10
PRG1_CPSW_RGMII2_RD1: R68.2 R221.1 U7.34 U18.Y10
PRG1_CPSW_RGMII2_RD2: R71.1 R230.2 U7.35 U18.Y11
PRG1_CPSW_RGMII2_RD3: R72.1 R229.2 U7.36 U18.V12
PRG1_CPSW_RGMII2_RSTN: U7.43 U34.4(Y)
PRG1_CPSW_RGMII2_RX_CTL: R73.2 R228.1 U7.38 U18.Y12
PRG1_CPSW_RGMII2_RXC: R51.1 U18.V10
PRG1_CPSW_RGMII2_RXC_R: R51.2 U7.32
PRG1_CPSW_RGMII2_TD0: U7.28 U18.Y6
PRG1_CPSW_RGMII2_TD1: U7.27 U18.AA8
PRG1_CPSW_RGMII2_TD2: U7.26 U18.Y9
PRG1_CPSW_RGMII2_TD3: U7.25 U18.W9
PRG1_CPSW_RGMII2_TX_CTL: U7.37 U18.V9
PRG1_CPSW_RGMII2_TXC: R23.1 U18.Y8
PRG1_CPSW_RGMII2_TXC_R: R23.2 U7.29
PRG1_CPSW_RGMII_INTN: R136.2 U7.44 U18.AA13 U19.44
PRG1_IEP0_EDC_LATCH_IN0: J5.8 U18.Y4
PRG1_IEP0_EDC_LATCH_IN1: J5.12 U18.V13
PRG1_IEP0_EDC_SYNC_OUT0: J5.6 U18.U3
PRG1_IEP0_EDC_SYNC_OUT1: J5.10 U18.T2
PRG1_MDIO0_MDC: U7.42 U18.W1 U19.42
PRG1_MDIO0_MDIO: R135.2 U7.41 U18.V2 U19.41
PRG1_RGMII1_RD0: U18.V4 U40.29
PRG1_RGMII1_RD1: U18.W5 U40.27
PRG1_RGMII1_RD2: U18.AA4 U40.25
PRG1_RGMII1_RD3: U18.Y5 U40.23
PRG1_RGMII1_RX_CTL: U18.AA5 U40.21
PRG1_RGMII1_RXC: U18.Y2 U40.19
PRG1_RGMII1_TD0: U18.V5 U40.41
PRG1_RGMII1_TD1: U18.W2 U40.39
PRG1_RGMII1_TD2: U18.V6 U40.38
PRG1_RGMII1_TD3: U18.AA7 U40.36
PRG1_RGMII1_TX_CTL: U18.Y7 U40.34
PRG1_RGMII1_TXC: R286.2 U40.32
PRG_CPSW_RGMII1_MUX_SEL: R62.1 R250.2 U18.Y20 U40.9 U40.10
QSPI_RST_N: U2.3 U31.4(Y)
R_BP_CONN_1_PORZ: R4.1 R8.2 U1.3
R_BP_CONN_2_PORZ: R2.2 R3.1 U1.6
SENCE3_IP: R188.2 U27.8
SOC_ADC0_AIN0: C28.1 R142.1 R143.2 U18.H21
SOC_ADC0_AIN1: C118.1 R152.2 R153.1 U18.F19
SOC_ADC0_AIN2: C110.1 R144.2 R145.1 U18.F21
SOC_ADC0_AIN3: C108.1 R146.2 R147.1 U18.F20
SOC_ADC0_AIN4: C33.1 R148.2 R149.1 U18.H20
SOC_ADC0_AIN5: C117.1 R150.2 R151.1 U18.E21
SOC_ADC0_AIN6: C35.1 R154.2 R155.1 U18.G20
SOC_ADC0_AIN7: C36.1 R156.2 R157.1 U18.E20
SOC_CLKIN: U11.4(Y) U18.D20
SOC_CLKIN_BUFF: R46.2 U11.2
SOC_CLKIN_BUFF_R: R46.1 U6.3
SOC_CPSW_RGMII1_TXC: R287.1 U18.W13
SOC_EMU0: U16.5 U18.C5
SOC_EMU1: U16.4 U18.B3
SOC_I2C0_SCL: R93.1 R141.1 R237.2 U17.6 U35.15
SOC_I2C0_SCL_BP: J5.17 R141.2
SOC_I2C0_SCL_RC: C47.1 R93.2 U18.B16
SOC_I2C0_SDA: R97.1 R158.1 R238.2 U17.5 U35.2
SOC_I2C0_SDA_BP: J5.19 R158.2
SOC_I2C0_SDA_RC: C161.1 R97.2 U18.B15
SOC_I2C1_SCL: J1.17 R88.2 U9.2 U18.A17
SOC_I2C1_SDA: J1.19 R82.2 U9.3 U18.B18
SOC_I2C1_TA_SCL: J15.36 R187.2 U9.7
SOC_I2C1_TA_SDA: J15.38 R182.2 U9.6
SOC_PRG1_RGMII1_TXC: R286.1 U18.W6
SOC_RESET_REQZ: TP24.1(TP) U13.2 U18.C17
SOC_RESETSTATZ: R234.2 TP13.1(TP) U18.E19
SOC_TCK: R162.1 U18.C6
SOC_TDI: U18.A3 U25.5
SOC_TDO: R271.1 U42.2
SOC_TMS: U18.B4 U25.6
SOC_TRST#: R120.2 U18.B6 U25.7
SPDT_MCAN/EQEP_MUX_SEL: R128.2 U22.1 U52.10
SPI0_CLK: J5.13 U18.B8
SPI0_CS1: J6.6 U18.B7
SPI0_D0: J6.12 U18.A8
SPI0_D1: J6.14 U18.C9
SPI3_CLK: J1.13 U18.N3
SPI3_CS0: J2.6 U18.E1
SPI3_CS1: U18.N4 U50.3 U52.11
SPI3_CS1/PRG0_PRU1_GPI11: J2.18 U50.5
SPI3_D0: U18.N1 U50.16
SPI3_D0/GPIO1_18: J2.12 U50.2
SPI3_D1: J2.14 U18.N2
SYNC1_OUT: J5.3 U18.A18 U50.8
SYNC2_OUT: J1.18 R140.2
SYNC3_OUT: J1.20 R131.2
SYS_BOOTMODE3: R16.1 SW4.1 U4.3 U26.2
SYS_BOOTMODE4: R27.1 SW4.2 U4.4 U26.3
SYS_BOOTMODE5: R33.1 SW4.3 U4.5 U26.4
SYS_BOOTMODE6: R47.1 SW4.4 U4.6 U26.5
SYS_BOOTMODE7: R52.1 SW4.5 U4.7 U26.7
SYS_BOOTMODE8: R66.1 SW4.6 U4.8 U26.8
SYS_BOOTMODE9: R69.1 SW4.7 U4.9 U26.9
TA_BOOTMODE_I2C_SCL: J15.37 R186.2 U26.12
TA_BOOTMODE_I2C_SDA: J15.39 R178.2 U26.13
TA_GPIO2: J15.31 R197.1 TP6.1(TP)
TA_GPIO3: J15.32 R196.1 TP3.1(TP) U28.1
TA_GPIO4: J15.33 R189.1 U26.1
TA_PORZN: J15.27 Q8.3 R211.1
TA_POWERDOWN: J15.26 R84.1
TA_PWR_EN: R251.2 U41.3
TA_SOC_INTN: J15.30 Q16.3 R202.1
TA_WARMRESETN: J15.28 Q7.3 R209.1
TCA6408_EXP_ADDR: R177.2 U26.16
TCA6408_EXP_INT: R191.1 U26.11
TEST_LED1_GREEN: Q6.3 R173.2 R216.1 U18.U19 U51.8
TEST_LED2_RED: Q5.3 R172.2 U18.A9
TEST_LED3_RED: Q9.3 R174.2 U18.D1 U52.1
TEST_LED4_GREEN: Q4.3 R165.2 U18.F3 U51.11
TIMER_IO0: R193.1 U18.K18 U50.12
TIMER_IO0/EHPWM3_B: J6.1 U50.10
TIMER_IO1: R19.1 U18.K20 U51.16
TIMER_IO1/EHPWM5_A: J6.3 U51.2
TIMER_IO2: R192.1 U18.J19 U51.3
TIMER_IO2/EHPWM8_B: J6.5 U51.5
TIMER_IO3: R194.1 U18.J18 U51.9
TIMER_IO3/EHPWM8_A: J6.7 U51.7
TIMER_IO4: R20.1 U51.12
TIMER_IO4/EHPWM7_B: J6.9 U51.10
TIMER_IO4_R: R20.2 U18.J20
TIMER_IO5: R21.1 U18.J21 U52.16
TIMER_IO5/EHPWM7_A: J6.11 U52.2
TM4C129_TCK: TP18.1(TP) U37.100
TM4C129_TDI: TP16.1(TP) U37.98
TM4C129_TDO: TP15.1(TP) U37.97
TM4C129_TMS: TP17.1(TP) U37.99
TUSB_ADDR: TP29.1(TP) U20.5
TUSB_ID: TP28.1(TP) U20.9
TUSB_INT_N: R110.1 U20.6
TUSB_OUT1: R107.1 U15.2
TUSB_OUT1_R: R106.1 R107.2 U20.7
TUSB_OUT2: R92.2 R104.1 U15.1
TUSB_OUT2_R: R104.2 R105.1 U20.8
TYPEC_CC1: J10.A5 U20.1
TYPEC_CC2: J10.B5 U20.2
TYPEC_DN: D6.1(CATHODE) J10.A7 J10.B7 L3.2
TYPEC_DP: D7.1(CATHODE) J10.A6 J10.B6 L3.3
UART0_HDR_CTS#: J17.2 U8.6
UART0_HDR_RTS#: J17.6 U8.12
UART0_HDR_RXD: J17.5 U8.3
UART0_HDR_TXD: J17.4 U8.9
UART1_HDR_CTS#: J13.2 U12.6
UART1_HDR_RTS#: J13.6 U12.12
UART1_HDR_RXD: J13.5 U12.3
UART1_HDR_TXD: J13.4 U12.9
USB0_DN: L3.1 U18.AA17
USB0_DP: L3.4(OUT2) U18.AA16
USB0_DRVVBUS: TP21.1(TP) U18.B19
USB0_ID: R83.2 U18.Y17
USB0_RCALIB: R239.1 U18.W17
USB0_VBUS: R116.2 R118.2 U18.V18
USBC_SHIELD: C266.1 J10.SH1 J10.SH2 J10.SH3 J10.SH4 J10.SH5 J10.SH6 R160.1
USER_INTN: TP12.1(TP) U13.5 U18.B9
VMON_MRN: C79.1 D5.1(CATHODE) Q8.1 Q8.2 Q8.5 Q8.6 Q8.8(S5) R171.1 SW1.1 SW1.3 U27.1
VMON_VSYS: C232.1 R255.1 R262.2 U18.G13
VPP_1V8: C38.1 TP51.1(TP) U14.5(OUT) U18.E16
VPP_1V8_REG_EN: J22.2 R90.2 U14.3
VPP_1V8_REG_EN_ON: J22.1 R593.1
VSYS_3V3: C3.2 C6.1 C7.1 C8.1 C9.2 C10.1 C12.1 C13.1 C14.1 C15.1 C16.2 C21.1 C22.1 C24.1 C27.1 C29.1 C32.1 C37.1 C40.1 C41.1 C43.1 C45.1 C46.1 C54.1 C59.1 C74.1 C84.1 C86.1 C90.1 C93.1 C94.1 C103.1 C106.1 C112.2 C119.1 C122.1 C124.1 C152.1 C159.1 C166.1 C207.1 C209.1 C218.1 C219.1 C220.1 C248.1 C258.1 C259.1 C265.2 C268.1 C270.1 C271.2 C272.2 C273.2 FB3.1 FB4.1 J1.1 J14.1 J16.10 R1.2 R3.2 R4.2 R5.2 R10.2 R12.1 R32.2 R35.1 R36.2 R37.2 R39.2 R40.2 R41.2 R43.2 R44.2 R45.2 R68.1 R73.1 R79.1 R80.1 R82.1 R88.1 R89.2 R91.1 R95.1 R112.2 R129.1 R134.1 R135.1 R136.1 R163.1 R164.2 R166.1 R167.1 R168.1 R169.1 R170.2 R181.2 R183.2 R201.2 R210.1 R218.1 R220.2 R223.2 R224.2 R225.1 R226.1 R227.1 R229.1 R230.1 R236.2 R237.1 R238.1 R252.2 R254.1 R257.2 R258.1 R261.1 R264.1 R265.1 R266.1 R268.1 R269.1 R275.2 R282.1 R283.1 R284.1 R285.1 R588.2 R590.2 R593.2 R598.2 R599.2 TP7.1(TP) U2.2 U3.4(VDD) U4.23 U4.24(VCCB2) U5.6 U6.6 U7.18 U7.30 U8.14(VCC) U9.1 U12.14(VCC) U13.8(VCC) U16.3 U16.6 U17.8 U19.18 U19.30 U22.10(VCC) U25.1 U30.10(VCC) U31.5 U32.2 U32.15(VCCB) U33.1 U33.2 U33.5 U34.5 U35.1(VCC) U39.1 U39.2 U39.4 U40.1 U40.8 U40.17 U40.30(VCC#30) U42.1 U43.5 U44.5 U45.1 U45.2 U46.2 U46.8 U50.14(VDD) U51.14(VDD) U52.14(VDD)
VSYS_3V3_CT: C81.1 U27.4
VSYS_3V3_FB: C40.2 R77.1 R80.2 U10.2
VSYS_3V3_R: C26.1 L1.2 R35.2
VSYS_3V3_SENSE: R195.1 R201.1 U27.9
VSYS_3V3_SW: L1.1 U10.6
VSYS_5V0: C25.1 C39.1 C51.1 C63.1 C64.1 C91.1 C123.1 C269.1 J1.2 J9.1 J12.4 J21.4 R11.1 R85.2 R86.1 R117.1 R161.2 R171.2 R188.1 R211.2 R262.1 R270.1 R272.1 R273.1 R274.1 R279.1 R280.1 R281.1 TP39.1(TP) U10.7(VIN) U14.1 U21.7(VIN) U23.7 U23.8(VOUT2) U27.14 U33.4 U46.15(VCCB)
VSYS_5V0_CT: C69.1 U23.6
VSYS_5V0_ON: LD9.1(CATHODE) U15.4(Y) U23.3
VUSB_5V0: C42.1 C57.1 C65.1 C66.1 C67.1 C226.1 FL1.2 R94.1 R105.2 R106.2 R110.2 R113.2 R251.1 TP53.1(TP) U15.5 U20.12(VDD) U23.1 U23.2 U23.4 U41.1
WDI: R9.2 U27.20
WDO: R11.2 U27.19(WDO)
XDS110_DEBUG_ID4: R98.1 U37.63
XDS110_DEBUG_ID5: R99.1 U37.62
XDS110_DEBUG_ID6: R100.1 U37.61
XDS110_DEBUG_ID7: R101.1 U37.60
XDS110_EMU0: R109.1 U16.8 U37.42
XDS110_EMU1: R108.1 U16.1 U37.43
XDS110_PROG_STAZ1: R114.2 U37.4
XDS110_PROG_STAZ2: R111.2 U37.3
XDS110_TCK: U25.13 U37.35
XDS110_TDI: U25.12 U37.38
XDS110_TDO: U37.37 U42.7
XDS110_TMS: U25.11 U37.36
XDS110_TRST#: U25.10 U37.40
XDS110_UART1_RXD: U37.33 U45.13
XDS110_UART1_TXD: U37.34 U45.11
XDS110_VBUS_DET: R212.1 R219.2 U37.1
XDS_RBIAS: R256.1 U37.59
XDS_RESET#: R246.2 TP26.1(TP) U37.70
XDS_SHIELD: C263.1 J20.6 J20.7 J20.8 J20.9 R159.1
XDS_USB_D_N: J20.2 U24.4 U24.7 U37.93
XDS_USB_D_P: J20.3 U24.5 U24.6 U37.94
XDS_USB_ID: J20.4 R231.2 U24.2 U24.9
XDS_VREF: C128.1 C129.1 R235.2 U36.3 U37.9
N17247526: LD15.2 R282.2
N17247539: LD14.2 R283.2
N17247599: LD13.2 R284.2
N17247637: LD12.2 R285.2
N29126233: R67.1 SW4.11
N29126235: R53.1 SW4.12
N29126237: R48.1 SW4.13
N29126239: R34.1 SW4.14
N29126243: R70.1 SW4.10
N29126245: R28.1 SW4.15
N29126269: R17.1 SW4.16
N30174920: R179.2 R180.2 U31.2
N30212600: LD2.1(CATHODE) Q5.1 Q5.2 Q5.5 Q5.6 Q5.8
N30212640: LD1.2 R167.2
N30212699: LD1.1(CATHODE) Q6.1 Q6.2 Q6.5 Q6.6 Q6.8
N30213674: LD2.2 R166.2
N30217069: C114.1 R222.1 U37.96
N30217074: R231.1 U37.95
N30217111: LD10.2 R111.1
N30217160: LD11.2 R114.1
N30310219: D3.3 R117.2 R118.1
N30339679: R15.1 U1.1 U27.15 U27.16 U27.18
N30360253: TP25.1(TP) U19.13 U19.48
N30371240: J19.11 R258.2
N30391563: J18.11 R210.2
N30391831: TP4.1(TP) U7.13 U7.48
N30573184: LD6.2 R79.2
N30625746: R271.2 U18.B5
N30693218: LD3.3 R168.2
N30693408: LD3.2 R169.2
N30703604: LD7.2 R86.2
N30811240: LD3.4(C2) Q9.1 Q9.2 Q9.5 Q9.6 Q9.8
N30811389: LD3.1 Q4.1 Q4.2 Q4.5 Q4.6 Q4.8
N30900913: R240.1 R244.1 U18.A15
N30979572: R162.2 U25.4
N31410611: LD8.2 R91.2
N31410626: LD8.1(CATHODE) Q3.1 Q3.2 Q3.5 Q3.6 Q3.8
N31458583: R119.2 U20.3
N31483389: LD9.2 R94.2
N32041451: R31.2 U5.4
N32341452: LD17.2 U52.7
N32341704: R599.1 U52.8
N32341897: R600.1 U52.9

Pads without a net: D3 2; J5 11; J10 A2 A3 A8 A10 A11 B2 B3 B8 B10 B11; J13 3; J15 4 5 6 8 9 10 11 12 13 14 15 17 18 19 20 21 22 23 24 29 35; J16 9; J17 3; J18 2; J19 2; SW4 8 9; U2 4 5 6 11 12 13 14; U4 14; U5 2; U6 7; U7 14 15 16 17 19 21 23 24; U10 4; U11 1; U14 4; U17 1; U18 H11 J13; U19 14 15 16 17 19 21 23 24; U21 4; U26 10; U27 3 11 13 17; U35 11 12 13 14; U36 2 4 5; U37 2 5 6 11 12 13 14 15 18 19 20 21 22 23 24 25 27 29 30 31 32 41 44 45 46 49 50 53 54 56 57 65 67 71 72 73 74 75 76 77 78 81 82 83 84 85 86 91 92 102 103 104 105 106 107 108 109 110 111 112 116 117 118 119 120 121 123 124 125 126 127 128; U38 2 5; U39 3; U41 4

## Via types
v1: diameter 0.457, hole 0.203, TOP to BOTTOM, 1407 vias
v2: diameter 0.406, hole 0.203, TOP to BOTTOM, 123 vias

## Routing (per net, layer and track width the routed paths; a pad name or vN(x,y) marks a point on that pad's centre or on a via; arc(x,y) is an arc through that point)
0V85_EN: length 3.6
  TOP w0.254: R125.1 48.23,-49.17 R127.2 48.21,-48.64 49.14,-47.71 U21.1
DGND: length 531.2
  TOP w0.102: v2(79.35,-45.8) 79.35,-45.86 U18.E6 ; U18.K6 81.35,-46.31 v2(80.89,-45.86) ; U18.H7 80.39,-45.75 v2(79.93,-45.29) ; U18.J11 80.94,-43.81 v2(81.39,-44.27) ; 83.39,-44.25 83.82,-43.81 U18.R11 ; v2(81.9,-42.35) 82.39,-41.84 U18.M15 ; U18.P15 83.39,-41.84 v2(82.88,-42.35) ; U18.K16 81.35,-41.32 v2(80.89,-41.77) 80.44,-41.32 U18.H16 ; 82.91,-43.81 v2(83.37,-44.27) ; v2(82.39,-44.83) 81.89,-44.33 U18.L10 ; U18.K7 81.39,-45.77 80.94,-45.31 ; v2(82.39,-43.36) 81.94,-43.81 U18.L11 ; U18.D17 78.39,-40.8 v2(78.9,-40.3)
  TOP w0.135: v1(44.96,-31.23) 44.94,-31.24 v1(44.2,-31.24) ; D4.2 74.6,-62.46 v1(74.32,-62.18)
  TOP w0.152: 76.78,-38.53 76.78,-38.71 76.81,-38.73 76.89,-38.66 77.09,-38.66 ; U18.R6 84.01,-46.2 84.01,-46.2 84.3,-45.92 v2(84.43,-45.92) 84.5,-45.92 U18.U6 ; U20.11 10.62,-46.49 10.44,-46.3 10.44,-46.3 v1(10.21,-46.08) 10.96,-46.08 U20.10 ; 76.72,-38.82 76.7,-38.82 76.66,-38.86
  TOP w0.203: v1(74.27,-35.23) 74.78,-35.74 75.11,-35.74 v1(75.83,-36.46) ; v1(26.87,-14.3) 26.89,-14.32 D2.2 ; 50.67,-46.48 v1(50.66,-46.47) 50.65,-46.48 v1(49.91,-46.48) 48.72,-46.48 ; v1(76.76,-36.46) 76.76,-35.13 v1(76.56,-34.92) ; D1.2 17.1,-13.73 v1(17.09,-13.74)
  TOP w0.254: U4.11 v1(28.51,-27.52) 28.51,-27.16 28.65,-27.02 U4.10 ; C64.2 34.47,-52.96 v1(34.85,-53.34) ; U18.N11 82.91,-43.81 ; U18.AA2 U18.AA1 U18.Y1 ; U22.5 154.6,-51.9 v1(154.61,-51.89) ; 83.39,-44.25 v2(83.37,-44.27) 83.38,-44.07 83.38,-43.83 U18.P11 ; U10.5 45.85,-30.57 v1(46.16,-30.26) ; U18.B1 U18.A1 U18.A2 ; v1(60.53,-37.08) 60.26,-36.82 U13.4 ; v1(44.83,-32.77) 44.43,-32.36 U10.3 ; U18.E11 78.89,-44.2 v2(78.83,-44.27) ; U4.13 v1(31.84,-28.88) ; U18.P16 U18.P15 ; U18.B21 U18.A21 U18.A20 ; v1(69.39,-50.48) 68.96,-50.48 68.74,-50.7 U25.15 ; U16.2 32.11,-40.53 32.17,-40.59 C45.2 v1(32.77,-41.2) ; v1(12.99,-40.89) 12.6,-40.5 12.6,-39.8 12.78,-39.62 U15.3 ; v2(82.88,-42.35) 82.88,-42.81 U18.N13 ; v1(64.75,-27.94) 64.67,-27.86 C20.2 ; v1(8.38,-46.2) 8.74,-46.56 C57.2 ; U24.3 U24.8 9.85,-52.52 9.86,-52.51 9.91,-52.51 10.17,-52.25 10.59,-52.25 10.82,-52.02 v1(10.82,-51.97) ; C11.2 v1(146.1,-25.34) ; v1(57.85,-25.64) 58.1,-25.88 C15.2 ; U18.AA20 U18.AA21 U18.Y21 ; U23.5 32.04,-52.85 32.03,-52.86 ; C59.2 v1(161.01,-49.53) ; 22.44,-55.63 21.95,-55.63 21.27,-56.31 J10.A12 ; C69.2 33.58,-53.02 33.53,-52.97 C63.2 ; v1(136.96,-52.27) 137.31,-52.27 137.51,-52.08 C61.2 ; C70.2 22.33,-54.86 ; v1(137.03,-33.22) 137.05,-33.21 137.33,-33.21 137.51,-33.03 C34.2 ; v1(50.53,-48.04) 50.14,-47.65 U21.3 ; U18.T14 84,-42.32 v2(83.94,-42.25) ; v1(156.57,-50.42) 156.58,-50.4 U22.9 ; C17.2 v1(146.1,-26.84) ; v1(51.88,-45.5) 51.57,-45.81 U21.5 ; C19.2 132.82,-26.98 v1(132.82,-26.97) ; C58.2 v1(146.1,-47.39) ; U4.12 v1(30.34,-28.88) ; J10.B12 15.77,-58.18 J10.A1 ; C23.2 v1(146.1,-28.34) ; C14.2 132.85,-25.85 v1(132.84,-25.86) ; C53.2 v1(146.1,-44.39) ; U18.M16 U18.M15 ; v1(68.73,-28.17) 68.73,-28.18 R54.2 ; U18.J5 U18.J6 v2(80.89,-45.86) ; C55.2 v1(146.1,-45.89)
  TOP w0.305: v2(78.83,-44.27) 78.78,-44.31 U18.D10 ; C60.2 69.14,-49.86 69.39,-50.11 v1(69.39,-50.48) ; v2(82.88,-45.86) 83.35,-45.86 U18.P7 ; v2(82.88,-45.86) 82.84,-45.81 U18.M7 ; v2(82.88,-45.86) 82.89,-45.87 U18.N6 ; U18.F17 79.38,-40.83 v2(79.38,-41.27) 79.85,-41.27 U18.G16 ; U18.F8 79.39,-45.76 v2(79.35,-45.8) ; U18.L12 82.35,-43.32 v2(82.39,-43.36) ; C123.2 122.61,-32.77 122.74,-32.77 v1(123.14,-33.17) ; U18.E13 U18.E11 ; U18.H7 U18.H6 ; U18.D17 U18.D16 ; v2(80.9,-45.28) 80.94,-45.31 U18.K8 ; U18.J16 v2(80.89,-41.77)
  TOP w0.33: v1(35.69,-21.51) 35.69,-21.82 C8.2 ; v1(69.75,-58.55) 69.39,-58.19 U25.3 ; C74.2 68.88,-59.61 v1(69.01,-59.49) ; C30.1 75.61,-31.85 v1(75.49,-31.98) ; R90.1 49.05,-37.43 C39.2 v1(48.46,-36.55) ; R47.2 12.19,-27.99 12.32,-28.12 v1(12.8,-28.12) ; v1(37.01,-23.72) 36.6,-24.13 R24.1 ; R119.1 v1(15.12,-48.67) ; U25.14 v1(69.39,-50.48) ; C49.2 57.51,-44.2 v1(57.61,-44.3) ; U12.13 100.47,-34.95 100.38,-35.04 C37.2 99.84,-34.47 v1(99.85,-34.47) ; C2.2 v1(29.21,-14.43) ; v1(141.96,-20.07) 141.66,-20.37 C6.2 ; C32.2 v1(8.41,-32.13) ; C65.2 27.86,-53.19 ; v1(72.64,-58.7) 72.64,-58.69 U25.8 ; C4.2 v1(33.71,-17.4) ; U5.5 60.43,-25.78 v1(60.94,-25.27) ; C13.2 v1(127.97,-25.78) ; v1(67.26,-65.74) 67.09,-65.74 C78.2 ; v1(99.85,-27.58) 99.84,-27.59 C24.2 100.38,-28.19 100.47,-28.1 U8.13 ; C12.2 84.21,-25.04 C10.2 ; C43.2 141.66,-39.42 v1(141.96,-39.12) ; v1(30.38,-19.48) 30.34,-19.52 C5.2 ; v1(15.09,-37.41) 15.57,-37.9 C42.2 ; R33.2 12.19,-26.41 12.37,-26.59 v1(12.8,-26.59) ; v1(54.99,-36.93) 54.99,-36.65 55.32,-36.32 C38.2 ; v1(63.75,-36.5) 63.65,-36.61 C41.2 ; v1(49.78,-37.21) 50.09,-36.91 U14.2 ; v1(68.73,-56.08) 68.74,-56.09 U25.2 ; C54.2 v1(132.85,-44.9) ; C56.2 v1(132.85,-46.03) ; C44.2 v1(25.76,-39.42) ; C21.2 v1(51.03,-29.08) ; C46.2 v1(141.33,-40.44) ; C7.2 v1(141.33,-21.39) ; C16.1 v1(127.97,-26.67) ; C31.2 6.92,-32.13 v1(7.01,-32.22) ; C22.2 v1(51.92,-29.08) ; U25.9 v1(72.64,-50.48) ; C1.2 v1(20.5,-14.84) ; C3.1 v1(99.47,-17.83) ; C29.2 v1(58.75,-30.43) ; C48.2 v1(56.62,-44.32)
  TOP w0.381: v1(65.88,-34.62) 65.2,-34.62 C33.2 ; R125.2 45.7,-48.83 v1(45.7,-47.75) ; v1(77.67,-36.27) v1(77.67,-35.41) ; U17.4 65.34,-46.88 65.52,-47.05 v1(65.56,-47.05) ; v1(73.23,-35.03) 73.23,-35.78 73.95,-36.5 v1(74.52,-36.5) ; R151.2 v1(54.58,-55.55) ; R155.2 v1(60.07,-55.55) ; v1(88.65,-37.36) v1(88.11,-37.9) 87.19,-38.82 U18.AA21 ; Q3.4 v1(3.64,-39.28) ; v1(11.43,-28.91) 11.39,-28.87 U9.4 ; R147.2 v1(49.1,-55.55) ; v1(62.03,-55.7) 62.43,-55.7 62.81,-55.32 R157.2 ; v1(73.81,-37.24) 73.53,-36.96 v1(73.15,-36.96) ; R142.2 v1(42.24,-55.55) ; v1(39.27,-46.13) R116.1 v1(38.49,-46.91) ; U18.A1 76.89,-49.17 76.89,-49.17 v1(76.89,-49.28) 76.78,-49.28 v1(76.38,-49.68) ; v1(73,-33.24) 73,-33.24 R78.1 ; v1(99.85,-34.47) 99.08,-34.47 R83.1 ; U11.3 75.22,-34.91 v1(75.21,-34.92) ; U12.7 v1(108.9,-31.71) ; U8.7 v1(108.9,-24.85) ; R153.2 v1(57.33,-55.55) ; U8.10 v1(100.44,-26.15) ; v1(72.64,-50.48) 71.73,-49.56 R126.1 ; U6.4 v1(117.69,-27.14) ; R145.2 v1(46.35,-55.55) ; C35.2 66.7,-34.62 v1(67.38,-34.62) ; U18.AA1 87.2,-49.12 v1(87.2,-49.15) 87.22,-49.15 v1(87.63,-49.56) ; U8.4 v1(106.24,-26.8) ; R9.1 12.05,-16.68 v1(12.3,-16.43) ; 76.89,-38.66 76.89,-38.67 U18.A21 76.72,-38.82 ; U12.1 v1(106.24,-35.6) ; v1(100.64,-33.07) 100.7,-33.01 U12.10 ; v1(9.07,-38.86) 9.58,-38.35 R92.1 ; C28.2 64.36,-34.6 v1(64.38,-34.62) ; C36.2 68.87,-34.6 v1(68.89,-34.62) ; Q3.7 v1(3.64,-40.16) ; U8.1 v1(106.24,-28.75) ; v1(37.86,-44.07) D3.1 36.92,-44.92 36.91,-44.93 v1(36.91,-44.96) ; U12.4 v1(106.24,-33.65) ; R149.2 v1(51.84,-55.55) ; U1.2 v1(29.57,-16.74)
  TOP w0.508: C76.2 v1(155.65,-61.03) ; v1(12.65,-25.1) 12.64,-25.1 12.6,-25.05 12.6,-25.04 12.19,-24.64 R27.2 ; LD10.1 1.83,-45.31 v1(1.83,-44.53) ; SW5.4 68.84,-66.29 v1(67.82,-66.29) ; R72.2 v1(134.73,-33.99) ; v1(141.43,-34.29) 141.79,-33.93 R74.2 ; R16.2 12.19,-23.14 12.6,-23.55 12.6,-23.55 v1(12.64,-23.59) ; R52.2 11.48,-28.85 v1(11.43,-28.91) ; v1(9.22,-10.46) 10.27,-10.46 SW1.2 ; R133.2 v1(134.73,-53.04) ; v1(51.88,-45.5) C51.2 ; SW3.4 34.35,-10.3 v1(34.47,-10.41) ; R66.2 v1(11.43,-30.35) ; R139.2 146.59,-52.98 146.58,-52.98 v1(146.58,-53.06) ; C77.2 v1(157.38,-61.03) ; C52.2 55.22,-45.24 v1(54.97,-45.5) ; R138.2 144.76,-52.98 144.75,-52.98 v1(144.75,-53.06) ; v1(1.78,-46.25) 1.82,-46.3 LD11.1 ; R22.2 v1(146.56,-23.84) ; v1(49.26,-30.26) 49.64,-29.88 C27.2 ; LD6.1 1.72,-33.03 v1(1.73,-33.02) ; R71.2 v1(133.2,-33.99) ; v1(17.2,-10.44) 17.06,-10.3 SW1.4 ; R49.1 v1(113.74,-27.69) ; v1(17.88,-10.46) 18.05,-10.3 SW2.2 ; R121.1 R122.1 v1(65.61,-49.61) ; R87.1 v1(70.89,-36.32) ; C71.2 153,-54.69 v1(153.9,-54.69) ; v1(153.9,-61.04) 153,-61.04 C75.2 ; C50.2 v1(53.32,-45.5) ; C18.2 63.18,-27.69 v1(62.21,-27.69) ; C47.2 v1(68.3,-40.51) ; v1(70.99,-47.42) 71.22,-47.42 71.73,-47.93 R120.1 ; U14.2 52.43,-36.91 v1(52.45,-36.93) ; SW2.4 25.77,-10.3 v1(25.93,-10.46) ; v1(26.57,-10.72) 26.99,-10.3 SW3.2 ; C73.2 v1(157.38,-54.68) ; R69.2 v1(11.43,-31.85) ; LD7.1 1.72,-35.06 v1(1.73,-35.05) ; R64.2 132.98,-29.5 132.22,-29.5 v1(132.21,-29.49) ; v1(84.2,-23.37) 84.21,-23.38 C10.2 ; R76.2 v1(145.01,-34.02) ; R132.2 v1(133.2,-53.04) ; v1(114.18,-26.93) 114.18,-25.94 U3.2 ; C26.2 v1(47.6,-30.26) ; R102.2 v1(146.56,-42.89) ; SW5.2 74.52,-66.29 v1(75.97,-66.29) ; v1(25.55,-53.39) 25.54,-53.4 C67.2 ; v1(132.28,-48.55) 132.29,-48.54 132.57,-48.54 132.98,-48.54 R123.2 ; R75.2 v1(143.29,-34.02) ; U2.10 v1(70.36,-20.32) ; v1(143.28,-53.06) 143.28,-52.98 143.29,-52.98 R137.2 ; R128.1 v1(149.23,-49.9) ; C72.2 v1(155.65,-54.68) ; C25.2 v1(46.16,-30.26)
  L02_GND1 w0.254: J10.B12 J10.G1 ; J10.G2 J10.B1
  BOTTOM w0.135: U52.6 118.49,-50.29 118.31,-50.11 118.18,-50.11 v1(117.83,-49.77) ; U51.6 115.46,-22.79 v1(115.24,-23.01) ; v1(94.48,-59.26) 94,-59.26 93.61,-59.64 U50.6 ; 119.11,-36.41 C124.2 ; C124.2 119.78,-35.77 ; C124.2 118.43,-35.77 ; v1(88.32,-59.97) 88.88,-60.53 C271.1 90.15,-60.53 90.23,-60.44 U50.13 ; 119.27,-46.49 C220.2 117.92,-46.49 ; C273.1 119.41,-54.25 119.41,-53.82 119.29,-53.71 U52.13
  BOTTOM w0.152: v1(17.14,-52.68) 17.14,-53.31 D7.2 ; 17.24,-23.53 v1(16.94,-23.82) ; U37.80 17.95,-39.19 17.86,-39.09 ; D6.2 v1(18.76,-52.66) ; 113.07,-23.67 113.15,-23.59 U51.13 113.68,-24.03 113.67,-24.05 ; U37.64 20.7,-46.69 v1(20.7,-45.54)
  BOTTOM w0.178: U42.4 68.44,-54.9 v1(68.45,-54.91) 68.45,-54.71 68.25,-54.51 U42.3 ; U37.114 27.5,-32.43 v1(27.5,-32.44) ; 35.83,-39.37 35.64,-39.19 U37.17 33.46,-39.19 v1(33.46,-39.19) ; 18,-44.79 U37.66 ; v1(27.1,-45.54) 27.1,-45.54 U37.48 27.1,-48.07 27.27,-48.24 ; C129.2 36.09,-36.6 35.88,-36.39 U37.10 ; R256.2 23.74,-48.96 23.74,-48.19 24.3,-47.63 U37.55 24.3,-45.54 v1(24.3,-45.54) ; U37.58 23.1,-45.54 v1(23.1,-45.54) ; U30.5 v1(104.69,-25.13) ; U42.5 65.98,-54.91 65.7,-54.63 v1(65.7,-54.54) 65.73,-54.51 U42.6
  BOTTOM w0.203: D5.2 9.28,-11.31 v1(9.27,-11.3) ; v2(83.37,-44.27) 83.41,-44.27 83.79,-44.65 C196.2
  BOTTOM w0.254: v1(24.18,-13.41) 24.22,-13.45 Q7.4 ; v1(24.18,-14.17) 24.29,-14.28 Q7.7 ; v1(117.69,-27.14) 117.45,-26.9 C103.2 ; U27.12 17.24,-23.53 ; Q4.7 v1(170.17,-11.44) ; v1(112.47,-40.77) 112.11,-41.12 C166.2 ; v1(16.38,-43.56) 16.38,-42.97 C181.2 ; C113.2 137.11,-33.21 137.05,-33.21 v1(137.03,-33.22) ; v1(4.22,-45.87) 4.11,-45.97 4.06,-45.97 3.81,-46.23 C226.2 4.39,-46.44 4.72,-46.1 U41.2 ; C190.2 79.68,-43.84 79.23,-43.84 78.83,-44.25 v2(78.83,-44.27) 78.61,-44.49 C202.2 ; C169.2 C168.2 ; C191.2 37.38,-43.59 v1(37.86,-44.07) ; C146.2 v1(9.07,-38.86) ; U45.15 35.58,-55.86 ; v1(16.97,-45.82) 16.87,-45.82 16.62,-45.57 C208.2 17.55,-45.24 18,-44.79 ; U45.7 32.33,-58.9 ; 27.27,-48.24 27.27,-48.84 27.02,-49.1 C242.2 ; v1(5.16,-27.74) 5.17,-27.72 J15.25 ; U26.6 v1(28.21,-19.92) ; C97.2 v1(132.82,-26.97) ; U32.7 v1(120.19,-24.21) ; v1(170.16,-10.49) 170.23,-10.56 Q4.4 ; U45.5 33.63,-58.74 ; C204.2 87.07,-45.44 86.38,-44.75 C203.2 ; C93.2 133.4,-25.86 v1(132.84,-25.86) ; C184.2 77.69,-42.85 77.29,-43.25 C192.2 ; C155.2 v1(9.07,-39.75) ; C198.2 82.7,-44.83 v2(82.39,-44.83) ; J15.34 v1(7.01,-23.22) ; C262.2 v1(38.11,-56.43) ; C269.2 146.26,-63.6 J12.5 ; v1(32.6,-56.13) 32.33,-55.86 U45.10 ; Q5.4 v1(165.73,-16.8) ; C223.2 77.26,-46.34 78.81,-46.34 78.97,-46.18 C210.2 ; C91.2 v1(16.94,-23.82) ; Q5.7 v1(165.73,-15.92) ; C248.2 112.14,-49.59 v1(112.32,-49.77) ; J15.7 v1(7.01,-36.72) ; J15.40 v1(7.01,-20.22) ; Q6.4 v1(170.55,-16.8) ; C270.2 v1(139.75,-63.34) ; U45.3 34.93,-61.32 35.05,-61.44 35.05,-61.79 C268.2 v1(34.42,-61.8) ; J15.16 v1(7.01,-32.22) ; C182.2 15.35,-43.56 v1(15.34,-43.56) ; v1(102.51,-45.14) 102.52,-45.14 C209.2 ; C215.2 81.1,-45.28 v2(80.9,-45.28) 80.64,-45.54 C214.2 ; C150.2 C149.2 ; U30.9 97.77,-23.63 97.71,-23.69 C90.2 v1(96.27,-23.69) ; C105.2 27.64,-28.96 27.56,-28.88 C104.2 ; C135.2 78.13,-37.44 v1(77.67,-36.98) ; Q6.7 v1(170.55,-15.92) ; v1(21.11,-26.72) 21.89,-26.72 22.28,-26.33 R195.2 ; U45.8 31.68,-58.87 ; Q9.4 v1(174.33,-15.15) ; Q9.7 v1(174.33,-16.03) ; U46.9 143.73,-59.8 v1(143.59,-59.94) ; U45.12 33.63,-55.89 v1(33.87,-56.13) ; U45.14 34.93,-55.86
  BOTTOM w0.305: Q15.4 160.75,-42.66 160.5,-42.42 v1(159.84,-42.42) 159.87,-42.44 Q15.7 ; C145.2 85.17,-39.16 84.89,-39.44 84.89,-40.05 C158.2 ; v2(80.89,-45.86) 80.89,-46.36 80.83,-46.43 80.83,-46.44 80.48,-46.79 C227.2 ; C172.2 81.65,-42.35 v2(81.9,-42.35) 82.14,-42.35 C175.2 ; C211.2 82.95,-45.92 v2(82.88,-45.86) 82.82,-45.92 C212.2 ; Q12.7 Q12.4 v1(164.89,-33.11) ; Q13.7 Q13.4 v1(164.89,-39.26) ; C186.2 82.47,-43.43 v2(82.39,-43.36) 82.32,-43.43 C187.2 ; C199.2 81.5,-44.17 v2(81.39,-44.27) 81.34,-44.21 C200.2 80.92,-43.45 C188.2 ; Q11.7 Q11.4 v1(164.89,-35.98) ; C201.2 79.91,-45.26 v2(79.93,-45.29) ; v2(82.88,-42.35) 83.15,-42.35 C173.2 ; v1(161.48,-46.04) Q14.4 Q14.7 ; C185.2 83.87,-42.32 v2(83.94,-42.25) 83.99,-42.3 84.61,-42.3 84.89,-42.03 C178.2 ; v1(120.4,-47.42) 120.19,-47.42 119.87,-47.1 C219.2 ; v1(165.44,-19.57) Q10.4 Q10.7 ; C210.2 v2(79.35,-45.8) ; 75.32,-40.49 C169.2
  BOTTOM w0.33: U44.2 164.52,-53.75 164.61,-53.66 164.61,-53.27 v1(164.04,-53.27) ; C102.2 30.01,-28.54 v1(30.34,-28.88) ; v1(11.72,-40.89) 11.39,-40.89 10.9,-41.39 C170.2 ; C253.2 83.11,-51.26 ; C231.2 141.71,-47.42 v1(141.2,-46.91) ; U28.3 37.48,-24.19 v1(37.01,-23.72) ; v1(69.8,-52.91) 69.39,-53.31 C259.2 ; C153.2 C144.2 C135.2 ; C169.2 74.66,-41.25 74.66,-41.24 C171.2 73.86,-41.14 v1(73.86,-40.11) ; v1(146.96,-29.9) 146.66,-29.59 C107.2 ; v1(87.2,-49.15) 87.2,-48.81 87,-48.62 C237.2 ; C86.2 v1(141.33,-21.39) ; C120.1 v1(15.09,-34.29) ; v1(36.42,-39.95) C151.2 35.83,-39.37 ; C150.2 82.5,-38 v1(82.6,-37.9) C141.2 ; C160.2 80.89,-40.78 v2(80.89,-41.77) 80.68,-41.55 C174.2 ; C265.1 v1(167.36,-57.07) ; C121.2 v1(37.8,-35.18) ; v1(73.52,-47.04) 73.52,-47.03 74.02,-46.53 C224.2 ; C53.2 v1(146.1,-44.39) ; C228.2 132.85,-46.92 v1(132.85,-46.03) C56.2 ; v1(82.6,-36.22) v1(82.6,-36.88) 83.06,-36.88 C134.2 C141.2 ; C162.2 78.55,-40.3 v2(78.9,-40.3) ; C152.2 v1(141.96,-39.12) ; v1(9.27,-11.3) 9.97,-11.3 10.42,-11.75 C79.2 ; v1(128.12,-47.04) 127.98,-47.19 C229.2 ; C141.2 83.19,-38.24 83.26,-38.31 C149.2 ; C96.2 141.46,-26.85 v1(141.2,-26.59) ; C256.2 137.11,-52.26 136.97,-52.26 v1(136.96,-52.27) 136.93,-52.27 136.91,-52.26 R267.2 ; 75.32,-40.49 75.21,-40.49 v1(74.83,-40.11) ; 88.11,-41.12 88.11,-41.29 87.6,-41.8 C176.2 ; C206.2 88.65,-46.43 ; 72.82,-49.23 73.6,-49.23 73.63,-49.2 73.68,-49.2 C236.2 ; v2(79.38,-41.27) 79.4,-41.25 C163.2 ; C194.2 73.76,-45.06 v1(73.58,-45.24) 73.38,-45.24 72.65,-44.51 C193.2 ; C147.2 80.08,-38.5 80.08,-38.11 80.08,-38.1 80.08,-37.74 79.96,-37.62 v1(79.96,-37.49) 79.91,-37.49 79.45,-37.95 C148.2 ; C55.2 v1(146.1,-45.89) ; v1(65.56,-47.05) 65.3,-47.31 C232.2 ; v1(121.67,-47.42) 120.88,-46.64 C218.2 ; 86.13,-40.84 86.49,-40.49 C157.2 87.48,-40.49 87.59,-40.6 C156.2 ; C167.2 C168.2 ; C17.2 v1(146.1,-26.84) ; C54.2 v1(132.85,-44.9) ; C131.1 15.09,-36.81 v1(15.09,-37.41) ; C129.2 v1(36.68,-37.16) ; TP2.1 34.17,-20.09 C88.2 ; C213.2 84.64,-46.03 84.53,-45.92 v2(84.43,-45.92) ; C189.2 76.93,-43.86 C192.2 ; C205.2 84.62,-42.3 84.61,-42.3 ; v1(76.76,-36.46) 76.5,-36.72 C138.2 C137.2 ; v1(73.15,-36.96) C142.2 ; 85.93,-37.01 v1(86.08,-36.86) ; v1(15.62,-33.15) 15.62,-32.97 16.05,-32.54 C114.2 ; C159.2 v1(141.33,-40.44) ; C235.2 83.09,-48.54 ; C244.2 77.96,-49.43 ; C249.2 83.09,-50.34 ; C11.2 v1(146.1,-25.34) ; U38.3 14.69,-43.32 15.06,-42.95 C182.2 C181.2 ; v1(28.65,-28.98) 28.63,-28.96 C105.2 ; C254.2 81.99,-51.35 ; C119.2 v1(141.43,-34.29) ; v1(146.96,-48.92) 146.69,-48.64 C238.2 146.01,-48.1 146.1,-48.01 v1(146.1,-47.39) C58.2 ; v1(77.67,-36.98) v1(77.67,-36.27) ; v1(141.2,-27.86) 141.71,-28.37 C100.2 ; C133.2 C140.2 C145.2 85.67,-38.81 85.95,-38.53 ; v1(141.2,-45.64) 141.46,-45.9 C217.2 ; v1(87.63,-49.56) 87.08,-49.56 87.03,-49.5 C246.2 ; v1(64.09,-53.39) 65.2,-53.39 C260.2 ; C139.2 75.62,-36.68 v1(75.83,-36.46) ; R203.1 96.58,-26.51 v1(96.57,-26.52) ; C116.2 81.97,-32.08 82.1,-31.95 C109.2 ; C250.2 77.96,-50.34 ; C128.2 v1(37.57,-37.16) ; C180.2 v1(37.42,-42.57) ; C85.2 v1(21.31,-20.73) ; v1(76.43,-26.19) 76.3,-26.31 C94.2 ; C251.2 81.99,-50.42 ; C204.2 87.48,-45.87 ; C130.2 v1(128.12,-36.47) ; C122.2 120.88,-35.92 v1(121.67,-36.7) ; v1(143.28,-53.06) 143.15,-53.19 C258.2 ; 17.86,-39.09 C154.2 v1(16.59,-39.09) ; C132.2 16.37,-36.78 v1(16.26,-36.66) ; C240.2 29.69,-48.72 v1(29.46,-48.95) ; 83.09,-49.45 C245.2 ; C239.2 81.99,-48.64 ; C112.1 v1(159.66,-33.25) ; C23.2 v1(146.1,-28.34) ; C234.2 77.96,-48.52 ; C177.2 86.69,-41 ; C247.2 81.99,-49.58
  BOTTOM w0.381: v1(137.41,-39.34) 137.43,-39.36 R242.2 ; v1(39.41,-37.35) 39.92,-36.84 U36.1 ; U35.8 159.88,-41.02 159.94,-40.95 R243.1 v1(161.48,-40.95) ; U43.3 139,-55.26 139.01,-55.24 v1(139.01,-55.22) ; v1(170.17,-11.44) 170.03,-11.3 R165.1 ; R221.2 132.99,-30.9 132.21,-30.11 v1(132.21,-29.49) ; v1(98.45,-31.67) 97.04,-31.67 R589.1 ; Q16.7 Q16.4 63.66,-65.62 v1(63.65,-65.63) ; v1(165.73,-15.92) 165.82,-15.83 R172.1 ; C156.2 88.11,-41.12 ; v1(119.13,-36.7) 119.13,-35.79 C124.2 ; v1(69.85,-30.14) 69.14,-30.14 C117.2 69.1,-30.11 v1(68.36,-30.11) 67.62,-30.11 C110.2 C108.2 ; C81.2 17.32,-13.97 v1(17.09,-13.74) ; v1(71.34,-30.12) 70.62,-30.12 C118.2 ; R592.2 31.48,-62.42 v1(31.47,-62.43) ; C82.2 v1(15.54,-13.75) ; C161.2 69,-40.51 v1(68.3,-40.51) ; C80.2 20.15,-14.49 v1(20.5,-14.84) ; v1(92.68,-36.31) 92.61,-36.23 R591.1 ; R199.2 v1(18.21,-26.75) ; C225.2 73.48,-47 v1(73.52,-47.04) ; R174.1 174.25,-16.12 v1(174.33,-16.03) ; R245.1 v1(148.08,-41.12) ; R228.2 136.97,-33.28 v1(137.03,-33.22) ; v2(75.26,-43.26) 75.46,-43.46 C189.2 ; R208.1 87.65,-25.98 87.66,-25.98 87.76,-25.88 v1(87.81,-25.88) 87.9,-25.88 R207.1 ; R234.1 72.82,-34.62 v1(73.23,-35.03) ; C98.2 132.82,-27.84 v1(132.82,-26.97) ; v1(82.6,-36.88) 82.35,-36.88 81.83,-37.4 C143.2 ; v1(96.57,-26.52) 96.56,-26.51 R204.1 v1(95.07,-26.51) R205.1 ; R260.2 132.99,-49.95 132.28,-49.24 v1(132.28,-48.55) ; v1(16.56,-27.48) 16.33,-27.71 R212.2 ; v1(89.71,-46.35) v1(90.47,-46.35) ; R173.1 170.64,-15.83 v1(170.55,-15.92) ; v1(92.05,-26.8) 91.76,-26.51 R206.1 ; Q8.4 v1(11.47,-16.43) ; Q8.7 v1(12.3,-16.43) ; C255.2 77.98,-51.38 v1(77.19,-52.17) ; R175.1 v1(22.28,-15.6) ; R241.1 v1(148.08,-39.6) ; v1(73.81,-37.24) 73.82,-37.23 C136.2 v1(74.52,-36.5)
  BOTTOM w0.508: C179.2 89.08,-41.2 v1(89.41,-40.87) v1(90.42,-40.87) v1(91.31,-40.87) ; R255.2 65.58,-48.81 65.58,-49.58 v1(65.61,-49.61) ; v1(72.64,-50.48) 72.82,-50.29 C241.2 72.82,-49.23 ; v1(138.46,-35.84) 138.45,-35.85 U34.3 ; v1(5.47,-17.95) J15.42 v1(4.18,-16.65) ; R250.1 v1(113.01,-46.78) ; v1(119.13,-47.42) 118.6,-46.89 C220.2 ; R177.1 v1(20.51,-19.42) ; C126.2 v1(77.67,-35.41) ; U35.16 v1(151.03,-32.13) ; U31.3 v1(77.64,-21.85) ; v1(7.62,-49.58) 7.63,-49.57 C243.2 v1(9.27,-49.57) ; v1(128.12,-35.2) 128,-35.33 C125.2 ; C109.2 v1(83.11,-31.22) ; C84.2 v1(141.96,-20.07) ; R276.1 v1(161.13,-57.27) ; v1(5.47,-42) J15.41 v1(4.18,-43.29) ; Y1.2 v1(14.38,-36.79) ; v1(104.69,-25.13) 105.3,-24.52 R190.1 ; v1(129.39,-35.2) 129.39,-34.78 128.91,-34.29 R232.2 ; v1(128.12,-45.77) 127.85,-46.05 C222.2 ; Y1.4 v1(10.22,-34.59) ; R184.2 v1(136.94,-19.4) ; C267.2 v1(168.33,-61.05)
  vias: v1(1.55,-30.73) v1(4.57,-22.25) v1(5,-23.88) v1(7.65,-55.19) v1(8.92,-55.19) v1(9.47,-54.13) v1(10.13,-61.49) v1(10.19,-55.19) v1(10.21,-64.85) v1(11.38,-54.13) v1(12.99,-42.16) v1(15.54,-19.43) v1(15.54,-20.57) v1(15.54,-21.72) v1(16.69,-19.43) v1(16.69,-20.57) v1(16.69,-21.72) v1(17.35,-53.97) v1(17.83,-19.43) v1(17.83,-20.57) v1(17.83,-21.72) v1(19.15,-54.18) v1(20.37,-36.58) v1(25.3,-19.66) v1(25.3,-20.68) v1(26.31,-19.66) v1(26.31,-20.68) v1(27.52,-54.86) v1(27.52,-56.13) v1(28.79,-56.13) v1(28.79,-57.4) v1(30.06,-56.13) v1(30.06,-57.4) v1(30.46,-23.75) v1(30.46,-25.27) v1(30.46,-26.8) v1(30.94,-53.62) v1(30.94,-54.38) v1(30.96,-51.13) v1(30.96,-52.27) v1(31.33,-56.13) v1(31.33,-57.4) v1(31.73,-23.75) v1(31.73,-25.27) v1(31.73,-26.8) v1(32.6,-57.4) v1(33.87,-57.4) v1(36.96,-16.41) v1(37.57,-10.95) v1(39.98,-31.83) v1(39.98,-33.1) v1(40.11,-10.95) v1(41.25,-31.83) v1(41.25,-33.1) v1(42.65,-10.95) v1(42.75,-48.79) v1(45.19,-10.95) v1(45.7,-46.48) v1(46.16,-31.53) v1(46.16,-32.8) v1(46.97,-46.48) v1(46.97,-47.75) v1(47.19,-66.17) v1(47.6,-31.53) v1(47.6,-32.8) v1(47.73,-10.95) v1(49.26,-31.53) v1(49.26,-32.8) v1(50.27,-10.95) v1(50.53,-30.26) v1(50.53,-31.53) v1(50.53,-32.8) v1(51.8,-30.26) v1(51.8,-31.53) v1(51.8,-32.8) v1(51.88,-46.77) v1(52.02,-48.18) v1(53.07,-30.26) v1(53.07,-31.53) v1(53.07,-32.8) v1(53.32,-46.77) v1(53.32,-48.04) v1(53.72,-36.93) v1(53.95,-66.04) v1(54.97,-46.77) v1(54.97,-48.04) v1(56.24,-45.5) v1(56.24,-46.77) v1(56.24,-48.04) v1(57.51,-45.5) v1(57.51,-46.77) v1(57.51,-48.04) v1(58.78,-45.5) v1(58.78,-46.77) v1(58.78,-48.04) v1(59.79,-48.3) v1(60.55,-65.99) v1(60.94,-26.29) v1(60.94,-27.69) v1(60.94,-29.21) v1(61.29,-48.04) v1(62.21,-29.21) v1(62.79,-48.18) v1(63.48,-29.21) v1(64.75,-29.21) v1(66.02,-27.94) v1(66.02,-29.21) v1(76.78,-65.61) v1(78.08,-52.12) v1(82.63,-50.98) v1(82.63,-51.99) v1(84.89,-65.71) v1(86.08,-35.81) v1(88.42,-36.02) v1(94.11,-39.76) v1(94.29,-38.48) v1(96.04,-38.28) v1(98.2,-17.83) v1(98.2,-19.1) v1(99.47,-19.1) v1(107.29,-42.11) v1(107.29,-43.38) v1(107.29,-44.65) v1(107.29,-45.92) v1(107.29,-47.19) v1(107.29,-48.46) v1(108.56,-42.11) v1(108.56,-43.38) v1(108.56,-44.65) v1(108.56,-45.92) v1(108.56,-47.19) v1(108.56,-48.46) v1(110.95,-24.05) v1(116.59,-36.7) v1(116.59,-37.97) v1(116.59,-47.42) v1(116.59,-48.69) v1(117.86,-36.7) v1(117.86,-37.97) v1(117.86,-47.42) v1(117.86,-48.69) v1(119.13,-37.97) v1(119.13,-48.69) v1(119.89,-22.98) v1(120.4,-36.7) v1(120.4,-37.97) v1(120.4,-48.69) v1(120.96,-23.12) v1(121.67,-37.97) v1(121.67,-48.69) v1(122.94,-36.7) v1(122.94,-37.97) v1(122.94,-47.42) v1(122.94,-48.69) v1(123.14,-32.28) v1(123.14,-34.06) v1(123.14,-43) v1(123.14,-43.89) v1(123.14,-44.78) v1(124.03,-32.28) v1(124.03,-33.17) v1(124.03,-34.06) v1(124.03,-43) v1(124.03,-43.89) v1(124.03,-44.78) v1(125.55,-31.14) v1(125.55,-41.85) v1(126.44,-31.14) v1(126.44,-41.85) v1(126.97,-21.89) v1(128.12,-37.74) v1(128.12,-48.31) v1(128.98,-47.17) v1(129.06,-48.27) v1(129.39,-36.47) v1(129.39,-37.74) v1(138.66,-25.32) v1(138.66,-26.59) v1(138.66,-27.86) v1(138.66,-44.37) v1(138.66,-45.64) v1(138.84,-46.74) v1(139.93,-25.32) v1(139.93,-26.59) v1(139.93,-27.86) v1(139.93,-44.37) v1(139.93,-45.64) v1(139.93,-46.91) v1(141.2,-25.32) v1(141.2,-44.37) v1(142.32,-59.94) v1(142.32,-60.96) v1(142.32,-61.98) v1(143.59,-60.96) v1(143.59,-61.98) v1(150.04,-33.91) v1(150.04,-36.45) v1(150.22,-49.17) v1(156.95,-17.14) v1(159.49,-17.14) v1(162.03,-17.14) v1(163.83,-55.3) v1(163.83,-56.57) v1(164.85,-55.3) v1(164.85,-56.57) v1(165.86,-55.3) v1(165.86,-56.57) v1(167.92,-40) v1(172.01,-39.98) v1(172.72,-39.4) v1(172.85,-62.66) v1(173.86,-61.93) v1(175.13,-61.93) v1(183.21,-37.57)
